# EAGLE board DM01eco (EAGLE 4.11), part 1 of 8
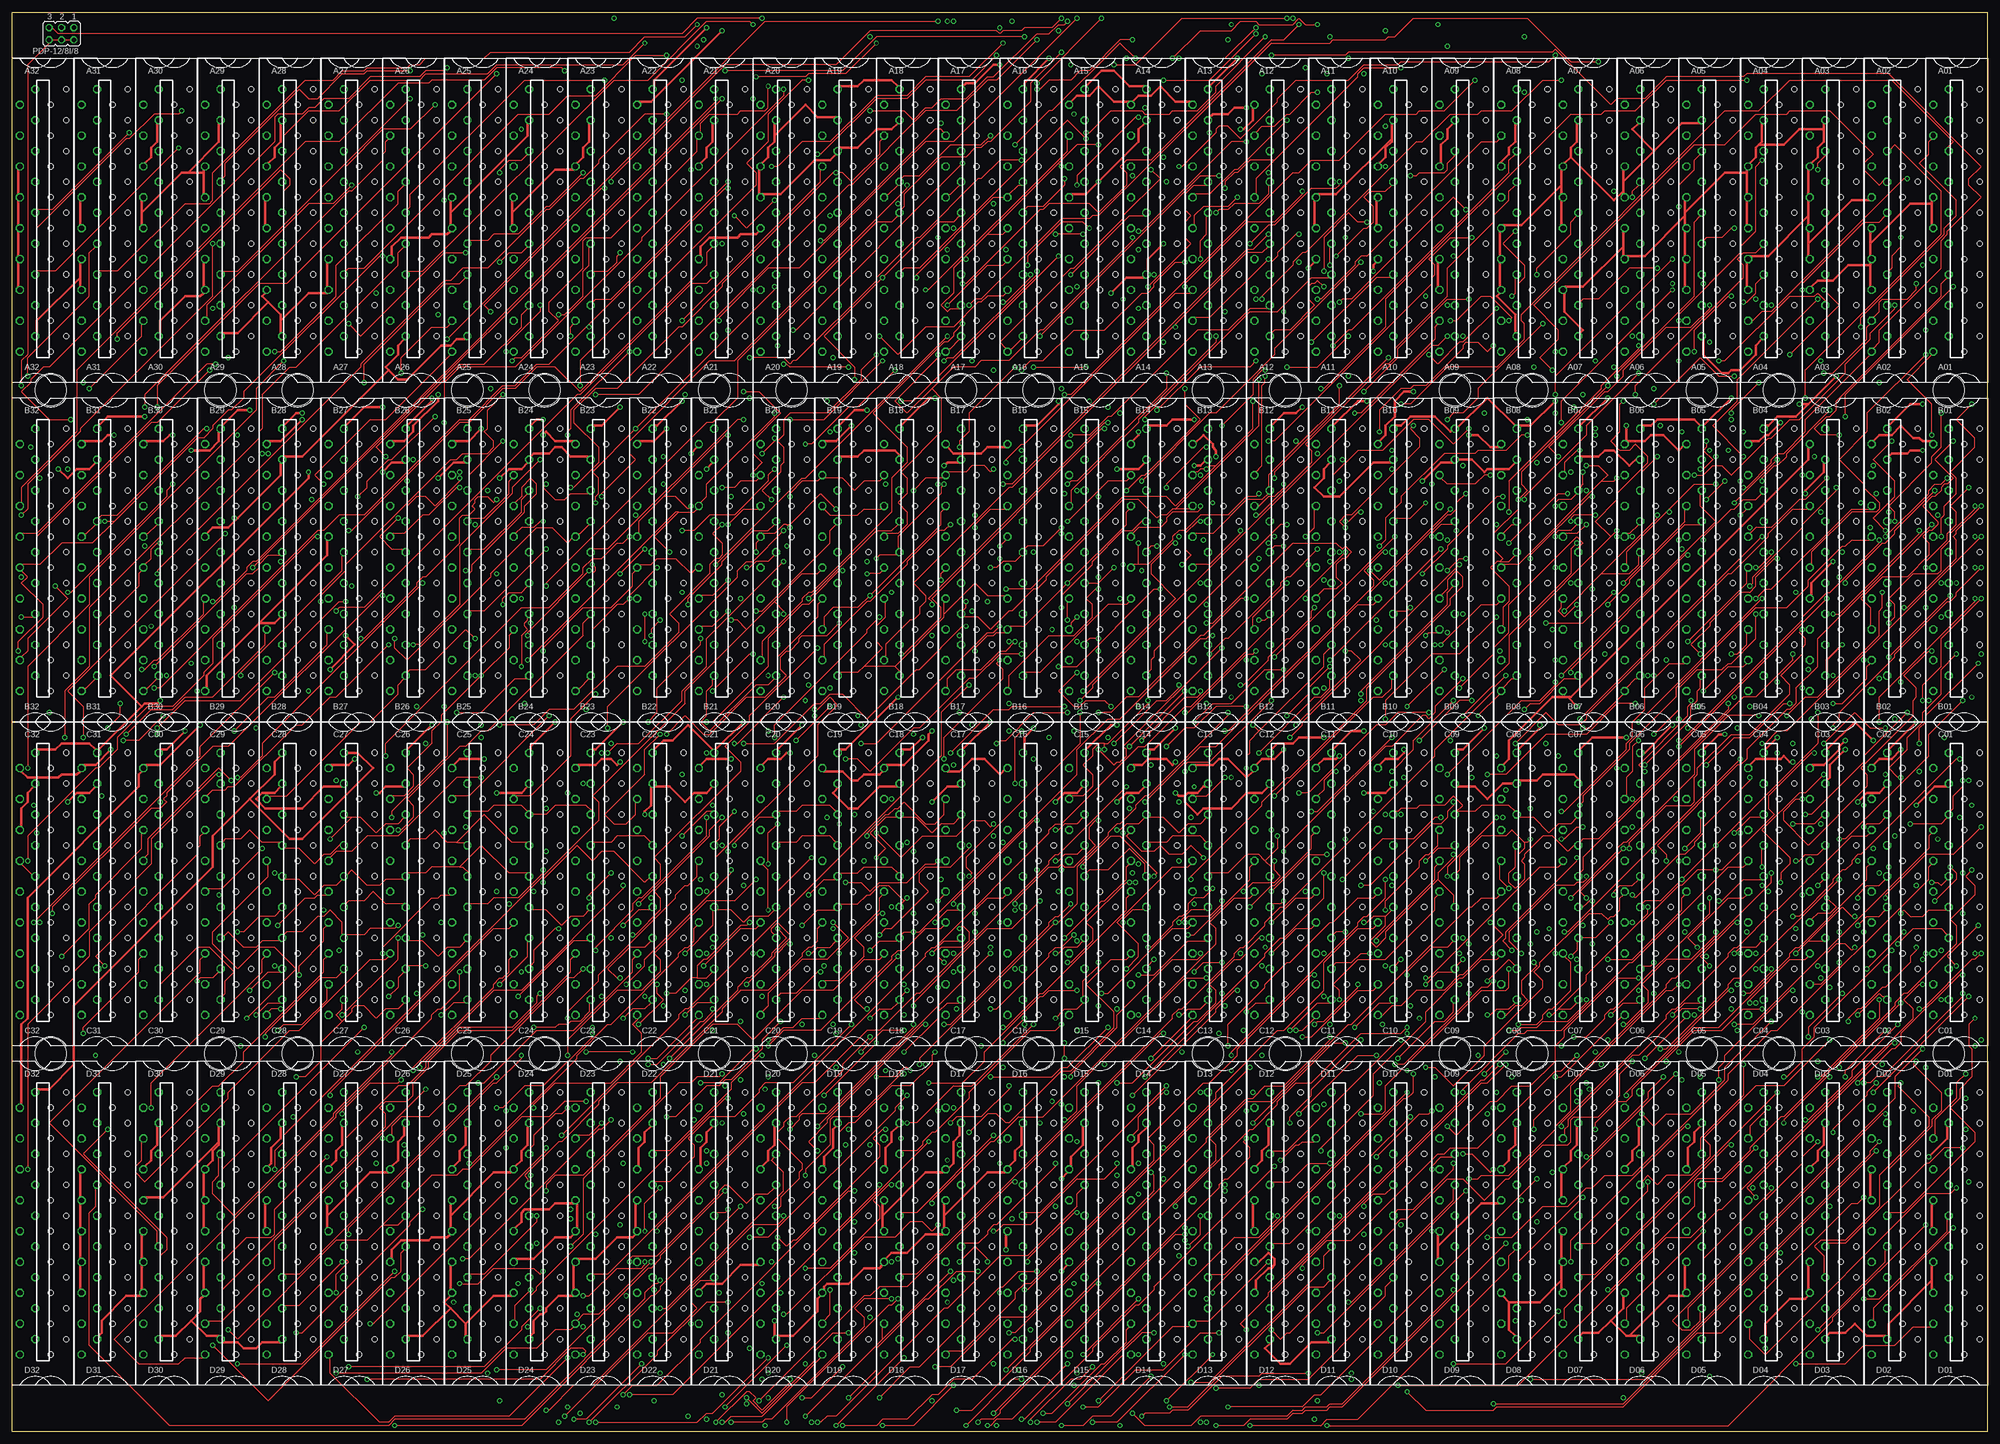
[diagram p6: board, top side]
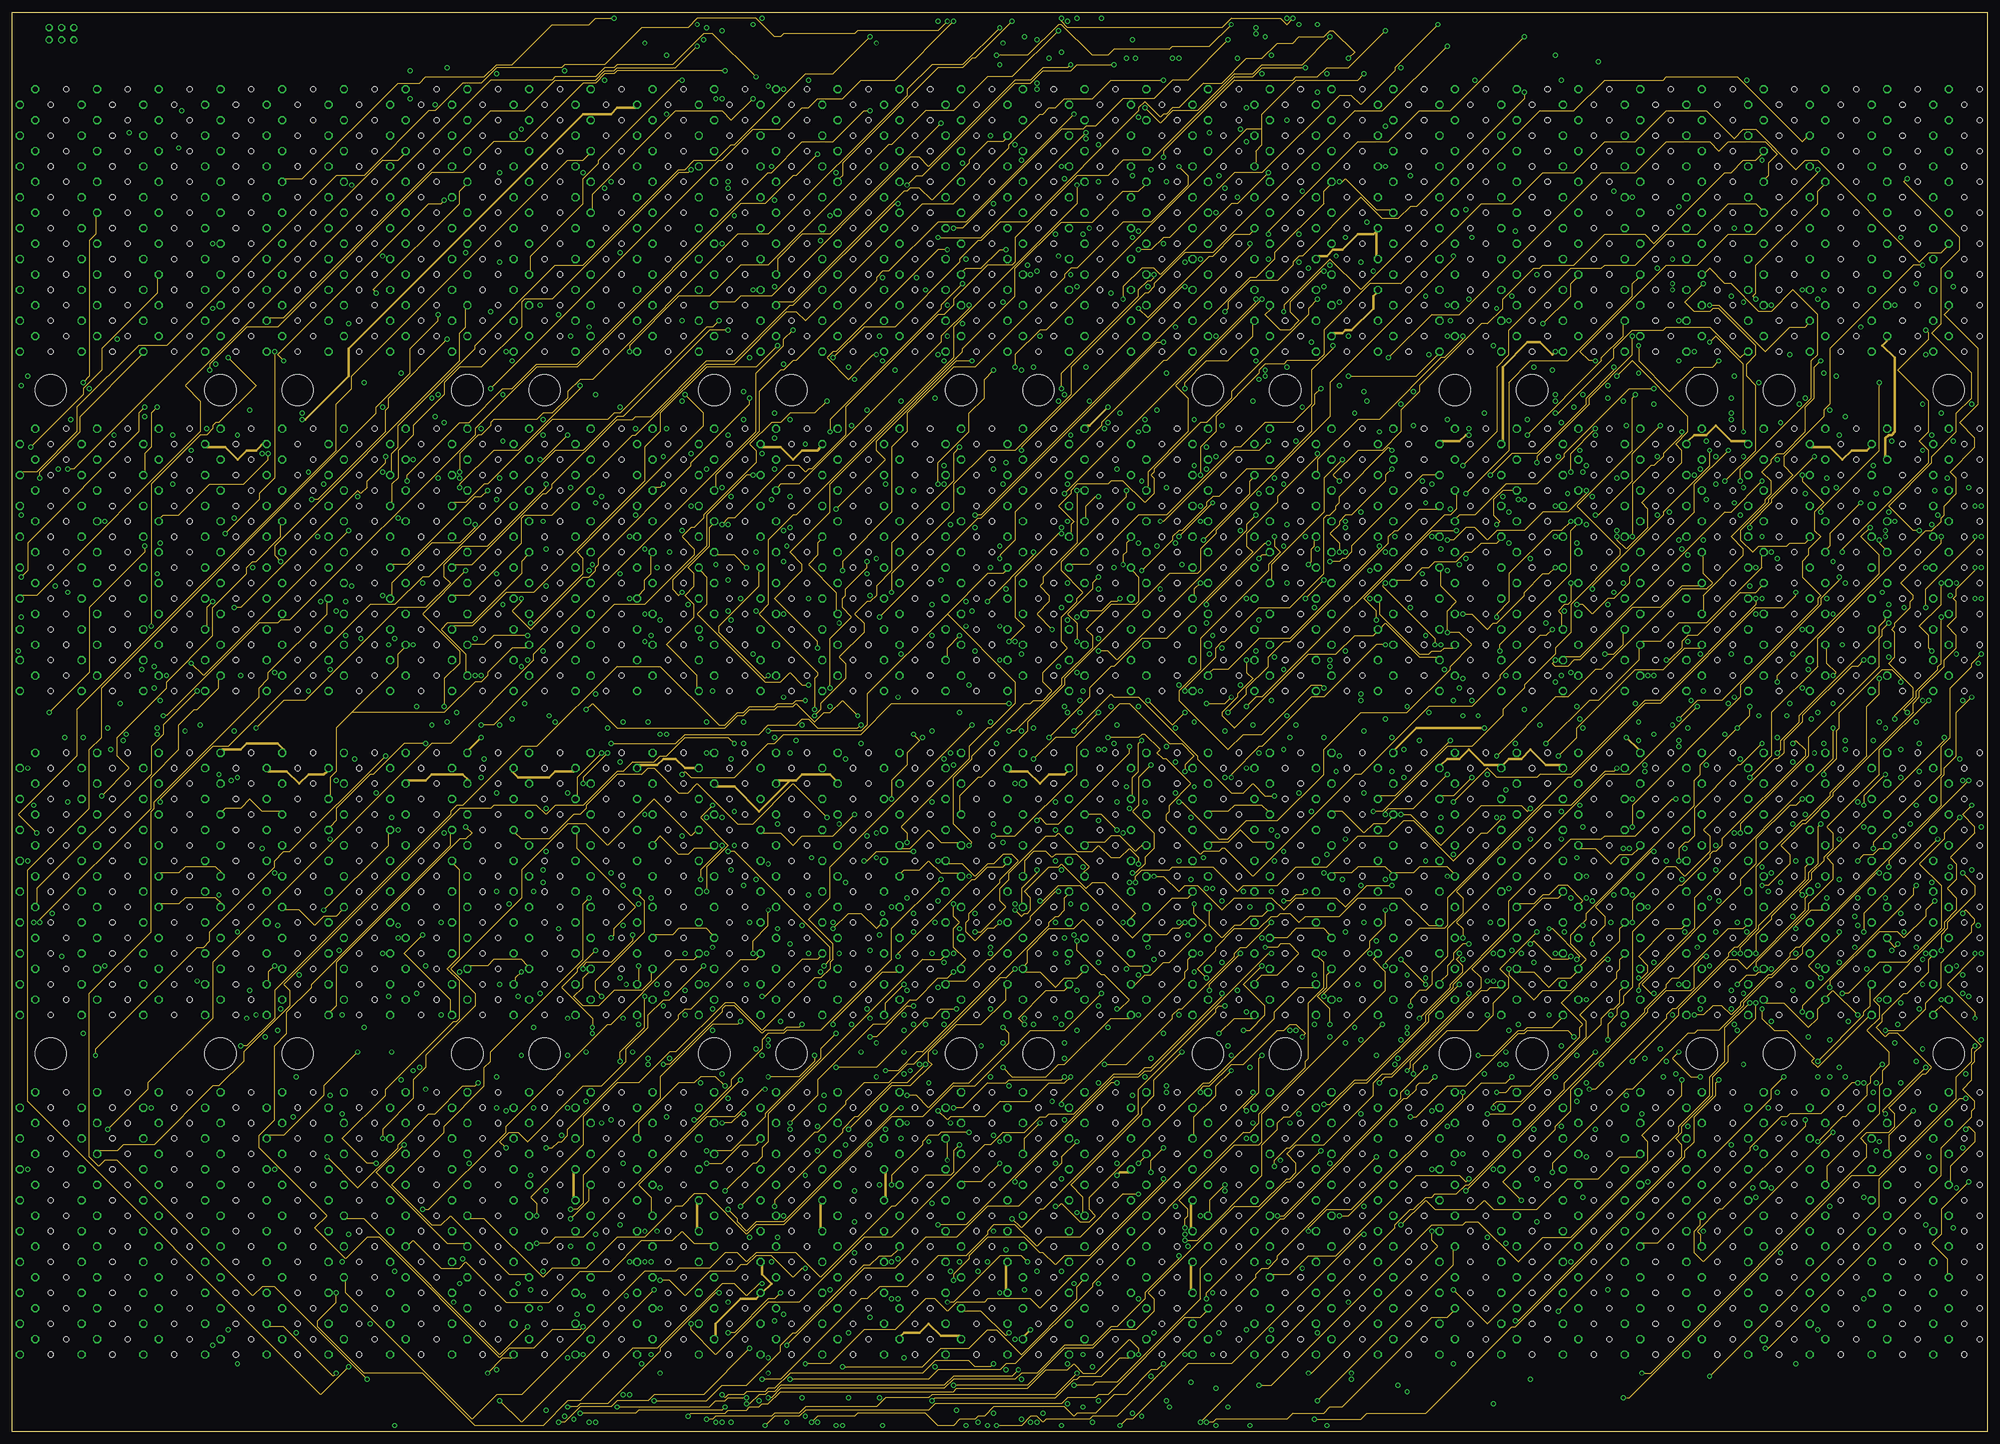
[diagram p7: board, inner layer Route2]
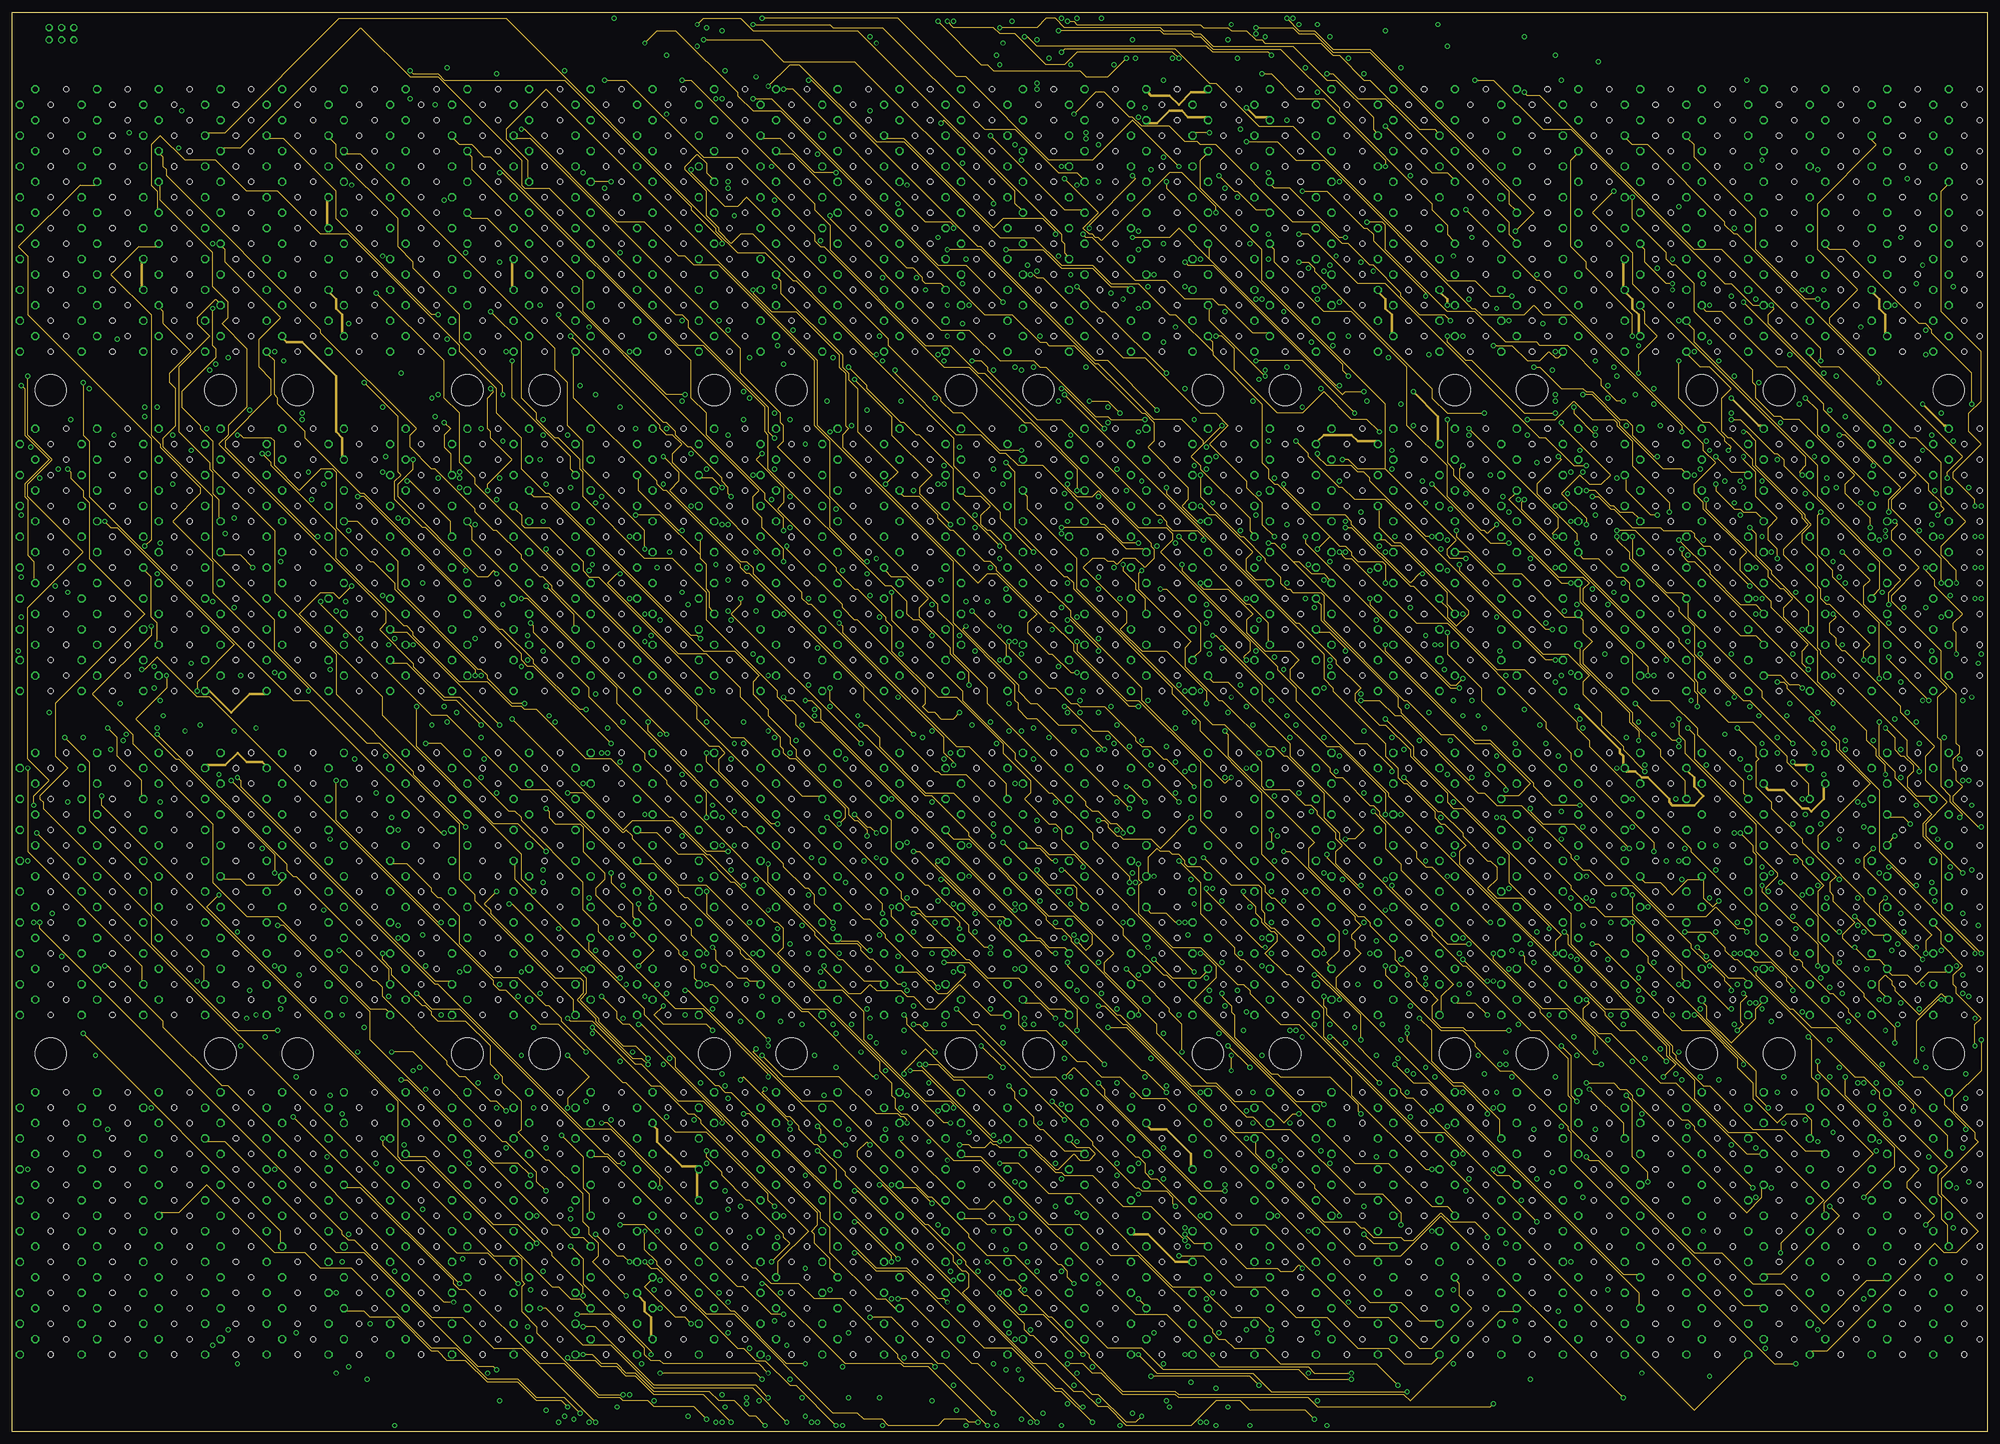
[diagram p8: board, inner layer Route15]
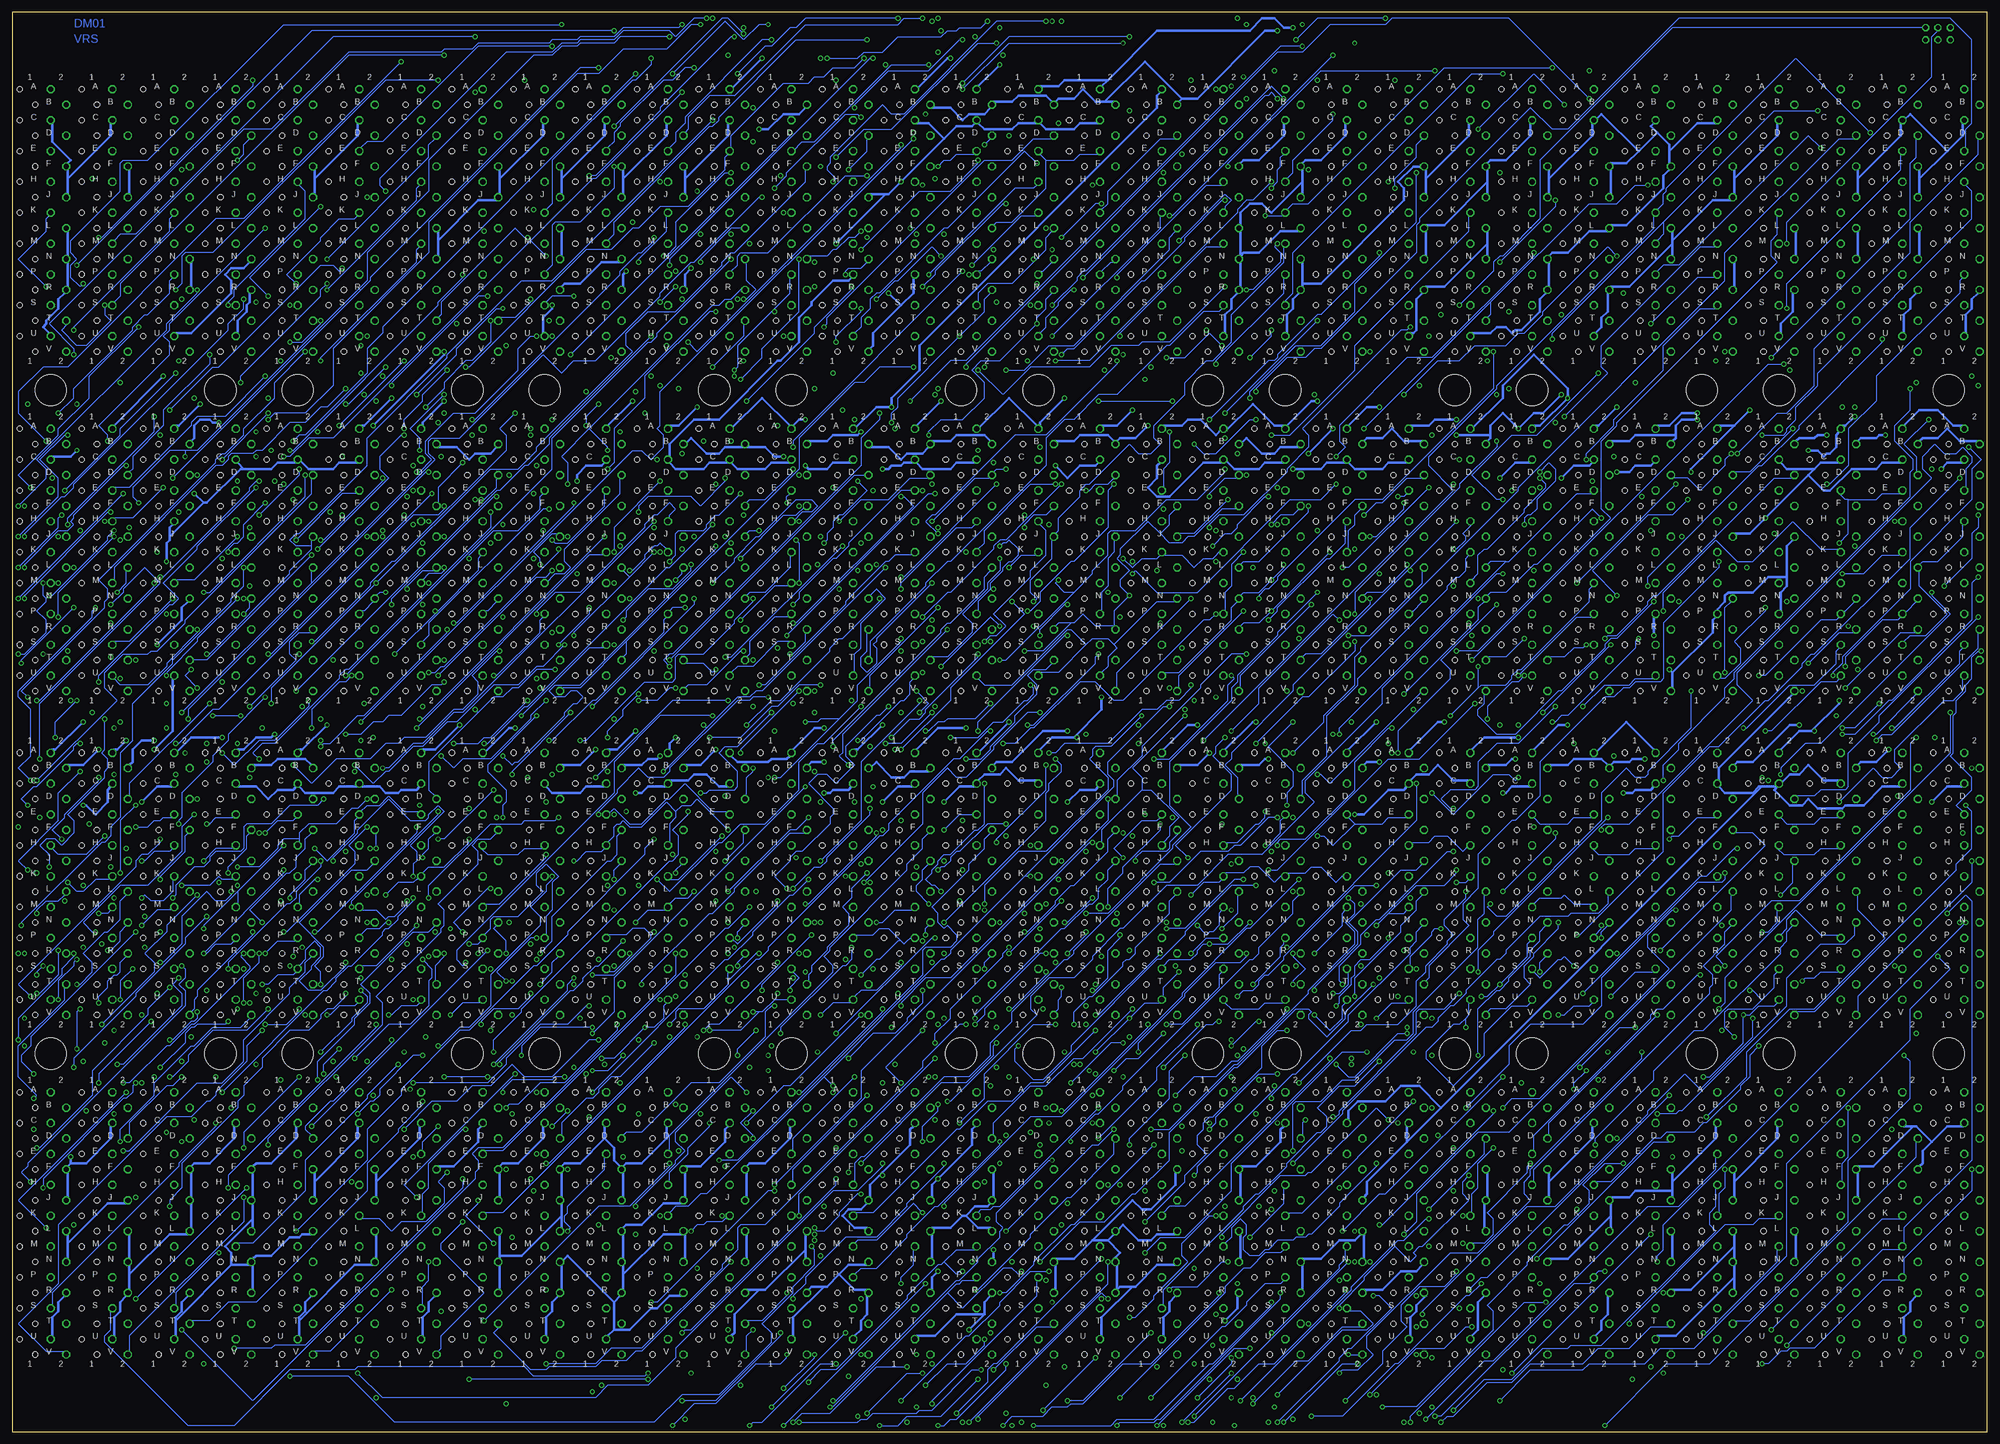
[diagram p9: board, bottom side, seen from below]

Size 406.4 x 292.1 mm. Coordinates in mm from the lower left corner, seen from the top.
Outline: 0,0 0,292.1 406.4,292.1 406.4,0 0,0
Copper layers (1*2*15*16): Top 0.035mm / dielectric 1.5mm / Route2 0.035mm / dielectric 0.15mm / Route15 0.035mm / dielectric 0.2mm / Bottom 0.035mm
Design rules "sierraproto": minimum track width 6mil, minimum drill 24mil, track to track 6mil, track to pad 6mil, pad to pad 10mil, via to via 6mil, smd to smd 6mil, copper to edge 25mil, drill to drill 10mil, minimum pad ring 10mil, minimum via ring 8mil, stop-mask expansion 0mil, vias tented up to drill 0mil, thermal gap 10mil
Net classes: 1 Supply: width 0.508 mm

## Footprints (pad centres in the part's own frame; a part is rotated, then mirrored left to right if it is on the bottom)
H807S = drill 1.092 octagon: A2 -1.587,28.575; B2 -4.763,25.4; C2 -1.587,22.225; D2 -4.763,19.05; E2 -1.587,15.875; F2 -4.763,12.7; H2 -1.587,9.525; J2 -4.763,6.35; K2 -1.587,3.175; L2 -4.763,0; M2 -1.587,-3.175; N2 -4.763,-6.35; P2 -1.587,-9.525; R2 -4.763,-12.7; S2 -1.587,-15.875; T2 -4.763,-19.05; U2 -1.587,-22.225; V2 -4.763,-25.4 | hole 1.092: 4.763,28.575; 1.587,25.4; 4.763,22.225; 1.587,19.05; 4.763,15.875; 1.587,12.7; 4.763,9.525; 1.587,6.35; 4.763,3.175; 1.587,0; 4.763,-3.175; 1.587,-6.35; 4.763,-9.525; 1.587,-12.7; 4.763,-15.875; 1.587,-19.05; 4.763,-22.225; 1.587,-25.4
JP3Q = drill 0.914 octagon: 1 -2.54,-1.27; 2 -2.54,1.27; 3 0,-1.27; 4 0,1.27; 5 2.54,-1.27; 6 2.54,1.27
CBLOCK = hole 6.452: 7.938,68.263; 42.862,68.263

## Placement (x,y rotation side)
A01  W021S  [H807S]  400.05,247.65 0 top
A02  W021S  [H807S]  387.35,247.65 0 top
A03  W021S  [H807S]  374.65,247.65 0 top
A04  W021S  [H807S]  361.95,247.65 0 top
A05  W021S  [H807S]  349.25,247.65 0 top
A06  W021S  [H807S]  336.55,247.65 0 top
A07  W021S  [H807S]  323.85,247.65 0 top
A08  W021S  [H807S]  311.15,247.65 0 top
A09  W021S  [H807S]  298.45,247.65 0 top
A10  W021S  [H807S]  285.75,247.65 0 top
A11  W021S  [H807S]  273.05,247.65 0 top
A12  S107S  [H807S]  260.35,247.65 0 top
A13  S107S  [H807S]  247.65,247.65 0 top
A14  W640S  [H807S]  234.95,247.65 0 top
A15  W640S  [H807S]  222.25,247.65 0 top
A16  S111S  [H807S]  209.55,247.65 0 top
A17  S111S  [H807S]  196.85,247.65 0 top
A18  S111S  [H807S]  184.15,247.65 0 top
A19  R202S  [H807S]  171.45,247.65 0 top
A20  W021S  [H807S]  158.75,247.65 0 top
A21  W021S  [H807S]  146.05,247.65 0 top
A22  EMPTYS  [H807S]  133.35,247.65 0 top
A23  W021S  [H807S]  120.65,247.65 0 top
A24  W021S  [H807S]  107.95,247.65 0 top
A25  W021S  [H807S]  95.25,247.65 0 top
A26  W021S  [H807S]  82.55,247.65 0 top
A27  W021S  [H807S]  69.85,247.65 0 top
A28  W021S  [H807S]  57.15,247.65 0 top
A29  W021S  [H807S]  44.45,247.65 0 top
A30  W021S  [H807S]  31.75,247.65 0 top
A31  W021S  [H807S]  19.05,247.65 0 top
A32  W021S  [H807S]  6.35,247.65 0 top
B01  EMPTYS  [H807S]  400.05,177.8 0 top
B02  R107S  [H807S]  387.35,177.8 0 top
B03  R603S  [H807S]  374.65,177.8 0 top
B04  S107S  [H807S]  361.95,177.8 0 top
B05  S107S  [H807S]  349.25,177.8 0 top
B06  S111S  [H807S]  336.55,177.8 0 top
B07  S107S  [H807S]  323.85,177.8 0 top
B08  S111S  [H807S]  311.15,177.8 0 top
B09  W005S  [H807S]  298.45,177.8 0 top
B10  S107S  [H807S]  285.75,177.8 0 top
B11  W005S  [H807S]  273.05,177.8 0 top
B12  S181S  [H807S]  260.35,177.8 0 top
B13  R107S  [H807S]  247.65,177.8 0 top
B14  S202S  [H807S]  234.95,177.8 0 top
B15  S107S  [H807S]  222.25,177.8 0 top
B16  S202S  [H807S]  209.55,177.8 0 top
B17  S202S  [H807S]  196.85,177.8 0 top
B18  S202S  [H807S]  184.15,177.8 0 top
B19  S202S  [H807S]  171.45,177.8 0 top
B20  S202S  [H807S]  158.75,177.8 0 top
B21  S202S  [H807S]  146.05,177.8 0 top
B22  R002S  [H807S]  133.35,177.8 0 top
B23  S111S  [H807S]  120.65,177.8 0 top
B24  W005S  [H807S]  107.95,177.8 0 top
B25  S107S  [H807S]  95.25,177.8 0 top
B26  S107S  [H807S]  82.55,177.8 0 top
B27  W640S  [H807S]  69.85,177.8 0 top
B28  W640S  [H807S]  57.15,177.8 0 top
B29  W640S  [H807S]  44.45,177.8 0 top
B30  S111S  [H807S]  31.75,177.8 0 top
B31  S111S  [H807S]  19.05,177.8 0 top
B32  S107S  [H807S]  6.35,177.8 0 top
C01  B141S  [H807S]  400.05,111.12 0 top
C02  B141S  [H807S]  387.35,111.12 0 top
C03  B141S  [H807S]  374.65,111.12 0 top
C04  B141S  [H807S]  361.95,111.12 0 top
C05  B141S  [H807S]  349.25,111.12 0 top
C06  B141S  [H807S]  336.55,111.12 0 top
C07  B141S  [H807S]  323.85,111.12 0 top
C08  B141S  [H807S]  311.15,111.12 0 top
C09  B141S  [H807S]  298.45,111.12 0 top
C10  B141S  [H807S]  285.75,111.12 0 top
C11  B141S  [H807S]  273.05,111.12 0 top
C12  B141S  [H807S]  260.35,111.12 0 top
C13  B141S  [H807S]  247.65,111.12 0 top
C14  B141S  [H807S]  234.95,111.12 0 top
C15  B141S  [H807S]  222.25,111.12 0 top
C16  B141S  [H807S]  209.55,111.12 0 top
C17  B141S  [H807S]  196.85,111.12 0 top
C18  B141S  [H807S]  184.15,111.12 0 top
C19  B141S  [H807S]  171.45,111.12 0 top
C20  B141S  [H807S]  158.75,111.12 0 top
C21  B141S  [H807S]  146.05,111.12 0 top
C22  B141S  [H807S]  133.35,111.12 0 top
C23  B141S  [H807S]  120.65,111.12 0 top
C24  B141S  [H807S]  107.95,111.12 0 top
C25  B141S  [H807S]  95.25,111.12 0 top
C26  B141S  [H807S]  82.55,111.12 0 top
C27  B141S  [H807S]  69.85,111.12 0 top
C28  B141S  [H807S]  57.15,111.12 0 top
C29  B141S  [H807S]  44.45,111.12 0 top
C30  B141S  [H807S]  31.75,111.12 0 top
C31  EMPTYS  [H807S]  19.05,111.12 0 top
C32  R302S  [H807S]  6.35,111.12 0 top
D01  W021S  [H807S]  400.05,41.27 0 top
D02  W021S  [H807S]  387.35,41.27 0 top
D03  W021S  [H807S]  374.65,41.27 0 top
D04  W021S  [H807S]  361.95,41.27 0 top
D05  W021S  [H807S]  349.25,41.27 0 top
D06  W021S  [H807S]  336.55,41.27 0 top
D07  W021S  [H807S]  323.85,41.27 0 top
D08  W021S  [H807S]  311.15,41.27 0 top
D09  W021S  [H807S]  298.45,41.27 0 top
D10  W021S  [H807S]  285.75,41.27 0 top
D11  W021S  [H807S]  273.05,41.27 0 top
D12  W021S  [H807S]  260.35,41.27 0 top
D13  W021S  [H807S]  247.65,41.27 0 top
D14  W021S  [H807S]  234.95,41.27 0 top
D15  W021S  [H807S]  222.25,41.27 0 top
D16  W021S  [H807S]  209.55,41.27 0 top
D17  W021S  [H807S]  196.85,41.27 0 top
D18  W021S  [H807S]  184.15,41.27 0 top
D19  W021S  [H807S]  171.45,41.27 0 top
D20  W021S  [H807S]  158.75,41.27 0 top
D21  W021S  [H807S]  146.05,41.27 0 top
D22  W021S  [H807S]  133.35,41.27 0 top
D23  W021S  [H807S]  120.65,41.27 0 top
D24  W021S  [H807S]  107.95,41.27 0 top
D25  W021S  [H807S]  95.25,41.27 0 top
D26  W021S  [H807S]  82.55,41.27 0 top
D27  W021S  [H807S]  69.85,41.27 0 top
D28  W021S  [H807S]  57.15,41.27 0 top
D29  W021S  [H807S]  44.45,41.27 0 top
D30  W021S  [H807S]  31.75,41.27 0 top
D31  W021S  [H807S]  19.05,41.27 0 top
D32  EMPTYS  [H807S]  6.35,41.27 0 top
PDP-12/8I/8  [JP3Q]  10.16,287.65 180 top
U$1  [CBLOCK]  0,9.53 0 top
U$2  [CBLOCK]  50.8,9.53 0 top
U$3  [CBLOCK]  101.6,9.53 0 top
U$4  [CBLOCK]  152.4,9.53 0 top
U$5  [CBLOCK]  203.2,9.53 0 top
U$6  [CBLOCK]  254,9.53 0 top
U$7  [CBLOCK]  304.8,9.53 0 top
U$8  [CBLOCK]  355.6,9.53 0 top
U$9  [CBLOCK]  0,146.05 0 top
U$10  [CBLOCK]  50.8,146.05 0 top
U$11  [CBLOCK]  101.6,146.05 0 top
U$12  [CBLOCK]  152.4,146.05 0 top
U$13  [CBLOCK]  203.2,146.05 0 top
U$14  [CBLOCK]  254,146.05 0 top
U$15  [CBLOCK]  304.8,146.05 0 top
U$16  [CBLOCK]  355.6,146.05 0 top

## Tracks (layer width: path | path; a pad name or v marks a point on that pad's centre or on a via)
1-CA_INH  (via drill 0.61)
  Top 0.152: v153.03,278.76 163.19,278.76 163.83,279.4 171.45,279.4 v177.8,285.75 | v210.82,276.22 211.46,276.22 213.36,278.13 217.81,278.13 219.71,280.03 221.62,280.03 227.97,286.38 v230.5,286.38
  Route2 0.152: v153.03,278.76 144.15,287.65 142.24,287.65 135.89,281.3 124.46,281.3 123.83,280.67 121.92,280.67 120.02,278.76 111.76,278.76 111.12,278.13 98.42,278.13 35.56,215.27 38.73,212.09 38.73,205.74 5.08,172.09 1.91,172.09 B32.N2
  Bottom 0.152: v177.8,285.75 201.29,285.75 v210.82,276.22 | v230.5,286.38 245.11,286.38 260.99,270.51 260.99,269.88 262.25,268.6 262.89,268.6 282.57,248.92 282.57,246.38 283.85,245.11 A10.M2
1-CA_INH0  (via drill 0.61)
  Top 0.152: v207.65,10.79 205.74,10.79 v196.22,1.27 | v147.32,26.67 142.88,26.67 132.72,16.51 132.72,15.88 v118.75,1.91 | v19.05,95.89 17.14,97.79 38.1,118.75 38.1,120.02 38.73,120.65 38.73,122.56 39.37,123.19 C29.F2
  Route2 0.152: v278.13,40.64 277.5,40.64 250.82,13.97 241.94,13.97 230.5,2.54 229.24,2.54 v227.97,1.27
  Route15 0.152: v278.13,40.64 280.04,38.73 283.85,38.73 D10.M2 | v90.81,26.67 88.9,26.67 44.45,71.12 43.18,71.12 31.11,83.19 31.11,84.46 19.68,95.89 v19.05,95.89
  Bottom 0.152: v227.97,1.27 224.16,1.27 222.25,3.18 215.26,3.18 v207.65,10.79 | v196.22,1.27 180.34,1.27 179.07,2.54 171.45,2.54 160.02,13.97 159.38,13.97 147.32,26.04 v147.32,26.67 | v118.75,1.91 118.75,3.18 95.25,26.67 v90.81,26.67
1-CA_INH1  (via drill 0.61)
  Top 0.152: v117.47,27.94 118.75,27.94 124.46,33.66 129.54,33.66 130.18,34.29 v130.18,34.92 | v169.54,1.27 v183.51,15.24 | v194.31,4.45 197.49,4.45 209.55,16.51 209.55,17.14 222.88,30.48 v223.52,30.48
  Route15 0.152: v42.55,110.49 40.01,107.95 111.12,36.83 111.12,36.2 117.47,29.84 v117.47,27.94 | v130.18,34.92 131.44,33.66 132.72,33.66 149.22,17.14 150.5,17.14 153.03,14.61 154.94,14.61 160.02,9.53 161.29,9.53 v169.54,1.27
  Bottom 0.152: v42.55,110.49 40.01,113.03 40.01,116.84 C29.J2 | v183.51,15.24 v194.31,4.45 | v223.52,30.48 223.52,31.75 220.98,34.29 220.98,37.47 D15.M2
1-CA_INH2  (via drill 0.61)
  Top 0.152: v51.44,120.02 43.18,111.76 40.01,111.76 C29.L2
  Route15 0.152: v83.19,90.17 86.36,87 92.08,87 121.92,57.15 122.56,57.15 124.46,55.24 v125.73,55.24
  Bottom 0.152: v51.44,120.02 52.07,120.02 57.78,114.3 59.05,114.3 v83.19,90.17 | v125.73,55.24 125.73,54.61 133.35,46.99 133.35,46.35 139.06,40.64 139.7,40.64 140.34,40.01 142.24,40.01 142.88,39.37 146.05,39.37 147.96,37.47 148.59,37.47 149.86,36.2 151.76,36.2 153.03,37.47 153.03,40.01 152.4,40.64 152.4,42.55 153.67,43.81 155.57,41.91 155.57,40.01 156.84,38.73 D20.M2
1-CA_INH3  (via drill 0.61)
  Route2 0.152: v80.64,59.05 74.93,53.34 89.53,38.73 93.34,38.73 D25.M2
  Bottom 0.152: v80.64,59.05 80.64,60.32 68.58,72.39 68.58,74.3 60.33,82.55 58.42,82.55 42.55,98.43 42.55,99.7 41.27,100.97 41.27,102.87 40.01,104.14 C29.N2
1-CA_INH4
  Top 0.152: D30.M2 29.84,38.73 29.84,41.27 7.62,63.5 38.73,94.62 38.73,97.16 39.37,97.79 C29.R2
1-CA_INH5  (via drill 0.61)
  Top 0.152: v10.79,142.88 10.79,152.4 15.88,157.48 15.88,169.55 50.8,204.47 50.8,205.74 51.44,206.38 51.44,213.36 57.15,219.08 58.42,219.08 79.38,240.03 79.38,242.57 80.64,243.84 A26.M2
  Route15 0.152: v10.79,142.88 15.88,137.8 15.88,125.73 28.57,113.03 28.57,106.68 39.37,95.89 39.37,92.71 C29.T2
1-CA_INH6  (via drill 0.61)
  Top 0.152: v3.17,217.17 3.17,220.98 15.88,233.68 15.88,242.57 17.14,243.84 A31.M2
  Route15 0.152: v4.45,128.91 4.45,130.81 7.62,133.98 3.17,138.43 3.17,169.55 14.61,180.97 3.17,192.41 3.17,194.94 8.26,200.03 3.17,205.11 v3.17,217.17
  Bottom 0.152: v4.45,128.91 3.17,127.64 3.17,120.02 6.35,116.84 6.35,115.57 35.56,86.36 39.37,86.36 C29.V2
-15V  (via drill 0.61)
  Top 0.508: v146.05,288.29 131.44,273.69 128.91,273.69 A22.B2 | A15.B2 217.81,273.69 219.07,274.95 221.62,274.95 223.52,276.86 226.69,273.69 229.87,273.69 A14.B2 230.5,273.69 231.78,274.95 234.31,274.95 236.22,276.86 239.4,273.69 242.57,273.69 A13.B2 | v252.73,267.97 253.37,267.97 255.27,269.88 255.27,272.41 A12.B2 | v33.02,205.11 32.38,205.11 31.11,203.84 27.3,203.84 B30.B2 | v59.69,208.28 55.24,203.84 52.7,203.84 B28.B2 | v20.95,205.11 19.68,205.11 18.41,203.84 14.61,203.84 B31.B2 | v96.52,206.38 93.98,203.84 90.81,203.84 B25.B2 | v109.22,205.11 109.86,205.74 111.76,203.84 115.57,203.84 B23.B2 | v299.72,205.11 301.62,205.11 304.17,202.56 306.07,202.56 B08.B2 | v172.72,207.01 169.54,203.84 167,203.84 B19.B2 | B16.B2 204.47,202.56 200.66,202.56 199.39,201.3 193.68,201.3 192.41,202.56 B17.B2 | v231.78,205.74 231.78,205.11 230.5,203.84 B14.B2 | v247.65,200.66 247.65,201.93 247.01,202.56 247.01,203.2 245.11,205.11 243.21,203.2 B13.B2 | v288.29,214 286.38,214 284.48,212.09 284.48,208.91 282.57,207.01 282.57,205.11 281.31,203.84 B10.B2 | v134.62,206.38 132.08,203.84 128.91,203.84 B22.B2 | v139.7,201.3 140.97,202.56 B21.B2 | v87.63,213.36 87.63,212.09 82.55,207.01 82.55,205.74 80.64,203.84 78.11,203.84 B26.B2 | C32.B2 1.91,135.89 3.17,134.62 9.53,134.62 10.16,135.25 13.34,135.25 13.97,135.89 C31.B2 14.61,137.16 17.14,137.16 v20.32,140.34 | D32.B2 1.91,67.31 1.91,83.82 3.17,85.09 3.17,109.86 26.04,132.72 26.04,135.25 26.67,135.89 C30.B2 27.3,137.16 30.48,137.16 v38.73,145.41 | v70.48,138.43 69.22,137.16 65.41,137.16 C27.B2 | v97.16,138.43 92.08,138.43 90.81,137.16 C25.B2
  Top 0.508: v377.19,142.24 375.92,140.97 375.92,140.34 372.75,137.16 370.2,137.16 C03.B2 | v388.62,140.34 386.71,138.43 384.18,138.43 382.9,137.16 C02.B2 | v366.39,137.8 365.76,137.8 364.49,139.06 363.86,138.43 358.77,138.43 357.5,137.16 C04.B2 | 332.11,203.84 335.92,203.84 337.19,205.11 339.73,205.11 342.9,201.93 344.17,203.2 B05.B2 | 332.11,203.84 B06.B2 332.11,203.84 | B01.B2 394.97,203.84 393.06,203.84 392.43,204.47 391.16,204.47 388.62,207.01 386.71,205.11 384.18,205.11 382.9,203.84 B02.B2 | v363.86,207.65 361.31,205.11 360.68,205.11 359.41,203.84 357.5,203.84 B04.B2 | C19.B2 167,135.89 170.81,135.89 172.72,133.98 173.99,133.98 175.26,135.25 178.44,135.25 179.07,135.89 C18.B2 179.71,137.16 183.51,137.16 188.59,142.24 188.59,143.51 v189.23,144.15 | v147.96,138.43 142.88,138.43 141.6,137.16 C21.B2 | v160.02,139.7 159.38,139.7 158.12,138.43 155.57,138.43 154.31,137.16 C20.B2 | C17.B2 192.41,135.89 194.94,135.89 197.49,138.43 200.03,138.43 203.2,135.25 204.47,136.53 C16.B2 | C13.B2 243.21,137.16 247.01,137.16 248.28,138.43 250.19,138.43 254,134.62 255.27,135.89 C12.B2 255.91,137.16 257.18,138.43 259.71,138.43 v261.62,140.34 | v273.05,139.06 272.42,138.43 269.88,138.43 268.61,137.16 C11.B2 | v286.38,140.34 286.38,139.7 285.12,138.43 282.57,138.43 281.31,137.16 C10.B2 | v239.4,137.8 238.76,137.16 237.49,138.43 233.68,138.43 232.41,137.16 230.5,137.16 C14.B2 | 320.04,151.13 316.87,151.13 307.98,142.24 307.98,138.43 306.7,137.16 C08.B2 | 320.04,151.13 320.68,151.13 369.57,200.03 369.57,202.56 B03.B2 | 320.04,151.13 v321.94,149.22 | v125.09,137.8 124.46,137.16 123.19,138.43 121.28,138.43 120.02,137.16 116.2,137.16 C23.B2
  Top 0.508: 332.11,203.84 v332.11,207.01
  Route2 0.508: B29.B2 40.01,202.56 43.81,202.56 46.35,200.03 48.26,201.93 50.16,201.93 52.07,203.84 B28.B2 | v299.72,205.11 299.08,205.11 297.81,203.84 294,203.84 B09.B2 | B20.B2 154.31,202.56 158.12,202.56 160.66,200.03 162.56,201.93 165.74,201.93 166.37,202.56 B19.B2 | v59.69,208.28 60.33,208.28 69.22,217.17 69.22,222.89 117.47,271.14 123.19,271.14 124.46,272.41 128.27,272.41 A22.B2 | C23.B2 115.57,135.89 111.76,135.89 110.49,134.62 104.14,134.62 102.87,135.89 C24.B2 | C28.B2 52.7,135.89 56.52,135.89 59.05,133.35 60.96,135.25 64.14,135.25 64.77,135.89 C27.B2 | B04.B2 356.87,203.84 353.69,203.84 350.52,207.01 348.62,205.11 346.07,205.11 344.81,203.84 B05.B2 | B03.B2 370.2,202.56 374.01,202.56 376.56,200.03 378.46,201.93 381.63,201.93 382.27,202.56 B02.B2 | C22.B2 128.91,137.16 132.72,137.16 133.99,138.43 136.53,138.43 138.43,136.53 140.97,136.53 C21.B2 | C16.B2 205.1,135.89 208.91,135.89 211.46,133.35 213.36,135.25 216.53,135.25 217.17,135.89 C15.B2 | C09.B2 294,137.16 295.27,138.43 297.81,138.43 299.72,140.34 302.89,137.16 306.07,137.16 C08.B2 306.7,137.16 307.98,138.43 310.51,138.43 312.42,140.34 315.6,137.16 318.77,137.16 C07.B2 | v317.5,222.25 316.87,221.62 314.32,224.16 311.79,224.16 306.7,219.08 306.7,203.84 B08.B2
  Route15 0.508: B10.B2 280.67,203.84 276.86,203.84 275.59,205.11 269.88,205.11 268.61,203.84 B11.B2 | v288.29,214 293.37,208.91 293.37,203.84 B09.B2 | C29.B2 40.01,137.16 43.81,137.16 46.35,139.7 48.26,137.8 51.44,137.8 52.07,137.16 C28.B2 | C05.B2 344.81,135.89 346.07,134.62 346.07,132.72 347.98,130.81 346.07,128.91 341.63,128.91 341,129.54 341,130.18 336.55,134.62 335.28,134.62 334.01,135.89 332.11,135.89 C06.B2 331.47,137.16 331.47,139.06 330.83,139.7 330.83,140.34 v321.94,149.22 | v366.39,137.8 367.03,137.16 369.57,137.16 C03.B2
  Bottom 0.508: v146.05,288.29 148.59,288.29 162.56,274.32 165.74,274.32 | 165.74,274.32 166.37,273.69 A19.B2 | 181.61,273.69 183.51,273.69 186.06,276.22 187.96,274.32 191.13,274.32 191.77,273.69 A17.B2 192.41,273.69 193.68,274.95 199.39,274.95 200.66,273.69 204.47,273.69 A16.B2 205.1,272.41 206.38,271.14 209.55,271.14 210.82,269.88 213.36,272.41 217.17,272.41 A15.B2 | 181.61,273.69 179.71,273.69 A18.B2 | v252.73,267.97 250.82,267.97 247.65,271.14 244.47,271.14 243.21,272.41 A13.B2 | 165.74,274.32 173.35,281.94 181.61,273.69 | B32.B2 1.91,203.84 5.71,203.84 8.26,206.38 10.16,204.47 13.34,204.47 13.97,203.84 B31.B2 | v33.02,205.11 34.92,205.11 35.56,204.47 38.73,204.47 39.37,203.84 B29.B2 | v59.69,208.28 62.87,208.28 64.14,207.01 64.14,205.11 | 64.14,205.11 64.14,204.47 64.77,203.84 B27.B2 | 64.14,205.11 72.39,205.11 73.66,203.84 77.47,203.84 B26.B2 | v20.95,205.11 22.23,205.11 22.86,204.47 26.04,204.47 26.67,203.84 B30.B2 | B23.B2 116.2,203.84 120.02,203.84 122.56,206.38 124.46,204.47 127.64,204.47 128.27,203.84 B22.B2 | 102.23,205.11 102.23,204.47 102.87,203.84 B24.B2 | 102.23,205.11 102.23,207.01 99.69,209.55 v96.52,206.38 93.34,209.55 91.44,209.55 v87.63,213.36 | v109.22,205.11 102.23,205.11 | B07.B2 318.77,202.56 314.96,202.56 312.42,200.03 311.15,201.3 307.98,201.3 306.7,202.56 B08.B2 | B11.B2 267.97,203.2 266.7,204.47 263.52,201.3 260.99,201.3 259.71,202.56 255.91,202.56 B12.B2 255.27,202.56 251.46,202.56 249.56,200.66 v247.65,200.66 | B21.B2 141.6,202.56 145.41,202.56 146.69,201.3 149.22,201.3 152.4,204.47 153.67,203.2 B20.B2 | v172.72,207.01 175.26,204.47 178.44,204.47 179.07,203.84 B18.B2 179.71,203.84 180.97,205.11 186.69,205.11 187.96,203.84 191.77,203.84 B17.B2
  Bottom 0.508: B16.B2 205.1,203.84 206.38,205.11 212.09,205.11 213.36,203.84 217.17,203.84 B15.B2 217.81,202.56 219.07,201.3 222.25,201.3 223.52,200.03 226.06,202.56 229.87,202.56 B14.B2 | v231.78,205.74 232.41,205.11 237.49,205.11 238.76,203.84 242.57,203.84 B13.B2 | v139.7,201.3 v134.62,206.38 | v20.32,140.34 22.86,137.8 26.04,137.8 26.67,137.16 C30.B2 | v70.48,138.43 73.03,138.43 73.66,137.8 76.83,137.8 77.47,137.16 C26.B2 78.11,137.16 79.38,138.43 85.09,138.43 86.36,137.16 90.17,137.16 C25.B2 | v97.16,138.43 97.79,138.43 99.06,137.16 102.87,137.16 C24.B2 | v377.19,142.24 379.73,142.24 381.63,140.34 381.63,137.8 382.27,137.16 C02.B2 | v388.62,140.34 391.8,137.16 394.97,137.16 C01.B2 | C04.B2 356.87,137.16 353.06,137.16 351.79,138.43 346.07,138.43 344.81,137.16 C05.B2 | v363.86,207.65 365.12,207.65 365.76,208.28 367.67,208.28 368.94,207.01 368.94,204.47 369.57,203.84 B03.B2 | v147.96,138.43 148.59,138.43 149.86,137.16 153.67,137.16 C20.B2 | v160.02,139.7 162.56,137.16 166.37,137.16 C19.B2 | C15.B2 217.81,135.89 221.62,135.89 222.88,134.62 225.43,134.62 228.6,137.8 229.87,136.53 C14.B2 | v261.62,140.34 264.8,137.16 267.97,137.16 C11.B2 | v273.05,139.06 273.69,138.43 275.59,138.43 276.86,137.16 280.67,137.16 C10.B2 | v286.38,140.34 289.56,137.16 293.37,137.16 C09.B2 | v239.4,137.8 241.94,137.8 242.57,137.16 C13.B2 | v189.23,144.15 194.31,144.15 200.66,137.8 203.84,137.8 204.47,137.16 C16.B2 | v125.09,137.8 127.64,137.8 128.27,137.16 C22.B2 | v38.73,145.41 40.64,145.41 48.26,137.8 51.44,137.8 52.07,137.16 C28.B2 | v317.5,222.25 317.5,221.62 v332.11,207.01
-AC_CLEAR  (via drill 0.61)
  Top 0.152: v261.62,119.38 261.62,120.02 282.57,140.97 283.85,140.97 290.19,147.32 290.83,147.32 291.46,146.69 292.74,147.96 292.74,149.22 v298.45,154.94 | v279.4,171.45 279.4,172.72 295.27,188.59 295.91,188.59 297.18,189.87 297.18,191.14 v299.08,193.04
  Route2 0.152: v299.08,193.04 307.98,201.93 307.98,215.9 312.42,220.34 320.04,220.34 333.38,233.68 333.38,236.22 334.64,237.49 A06.P2
  Route15 0.152: v261.62,119.38 262.89,119.38 276.23,106.05 276.23,105.41 277.5,104.14 275.59,102.23 275.59,101.6 276.23,100.97 276.23,99.7 277.5,98.43 272.42,93.34 272.42,91.44 331.47,32.38 334.64,32.38 D06.P2 | v298.45,154.94 297.18,153.67 295.91,153.67 279.4,170.18 v279.4,171.45
-BAC0  (via drill 0.61)
  Top 0.152: v401.95,73.66 400.05,71.75 400.05,68.58 395.61,64.14 395.61,60.96 D01.D2 | v388.62,134.62 387.99,134.62 386.08,136.53 389.89,140.34 389.89,142.88 393.06,146.05 393.06,147.96 396.88,151.77 396.88,156.84 v400.05,160.02 | v393.7,177.8 393.7,179.07 398.14,183.52 398.14,184.78 400.05,186.69 400.05,189.23 398.78,190.5 v402.59,194.31 | v380.37,227.33 380.37,229.24 397.51,246.38 397.51,247.65 400.05,250.19 400.05,253.37 392.43,260.99 394.33,262.89 394.33,265.43 394.97,266.06 A01.D2
  Route2 0.152: v381,102.87 381,106.68 v396.24,121.92
  Route15 0.152: v400.05,160.02 400.05,164.47 399.42,165.1 399.42,166.37 401.32,168.28 395.61,173.99 395.61,175.26 393.7,177.16 v393.7,177.8
  Bottom 0.152: v401.95,73.66 404.5,76.2 404.5,77.47 402.59,79.38 402.59,81.28 v381,102.87 | v396.24,121.92 398.14,123.83 395.61,126.37 395.61,127 388.62,133.98 v388.62,134.62 | v402.59,194.31 405.13,196.85 396.88,205.11 396.88,206.38 390.52,212.72 390.52,217.17 v380.37,227.33
-BAC1  (via drill 0.61)
  Top 0.152: v274.32,186.06 273.05,187.33 274.32,188.59 275.59,188.59 289.56,202.56 289.56,204.47 287.65,206.38 v288.29,207.01 | v285.75,211.46 287.65,211.46 295.27,219.08 305.44,219.08 311.15,224.79 311.15,227.97 310.51,228.6 310.51,229.87 352.43,271.78 359.41,271.78 365.76,278.13 386.71,278.13 399.42,265.43 398.14,264.16 A01.E2
  Route15 0.152: v274.32,186.06 275.59,186.06 287.65,173.99 288.29,173.99 305.44,156.84 311.15,156.84 321.94,146.05 321.94,144.78 324.49,142.24 324.49,140.97 345.44,120.02 345.44,119.38 358.77,106.05 358.77,100.33 398.14,60.96 398.14,57.78 D01.E2
  Bottom 0.152: v288.29,207.01 288.29,208.91 v285.75,211.46
-BAC2  (via drill 0.61)
  Top 0.152: v386.08,166.37 387.35,167.64 387.35,170.18 386.08,171.45 391.16,176.53 396.24,176.53 396.88,177.16 396.88,181.61 398.78,183.52 398.78,184.78 403.86,189.87 v403.86,190.5
  Route2 0.152: v401.95,62.23 402.59,62.87 403.86,61.59 403.86,59.69 398.78,54.61 398.78,51.43 D01.H2 | v355.6,123.19 355.6,125.09 369.57,139.06 369.57,142.88 384.18,157.48 384.18,163.19 384.81,163.83 384.81,165.1 v386.08,166.37
  Route15 0.152: v401.95,62.23 401.95,62.87 397.51,67.31 397.51,68.58 393.06,73.03 391.16,73.03 377.82,86.36 377.82,87 374.65,90.17 374.01,90.17 368.3,95.89 368.3,96.52 367.67,97.16 367.03,97.16 365.76,98.43 365.76,99.7 358.77,106.68 358.77,118.75 358.14,119.38 358.14,120.65 v355.6,123.19 | v403.86,190.5 403.86,191.77 399.42,196.22 399.42,197.49 405.13,203.2 402.59,205.74 402.59,209.55 405.13,212.09 405.13,222.25 396.88,230.5 396.88,255.27 398.14,256.54 A01.H2
-BAC3  (via drill 0.61)
  Top 0.152: v381,27.3 384.18,27.3 398.14,41.27 398.14,43.81 D01.K2 | v310.51,98.43 307.98,100.97 307.98,102.87 317.5,112.4 321.31,112.4 321.94,113.03 323.21,113.03 323.85,113.67 v323.85,114.3 | v340.36,117.48 340.36,118.75 338.45,120.65 354.96,137.16 355.6,137.16 356.87,138.43 356.87,140.34 365.12,148.59 365.76,148.59 367.03,149.86 367.03,153.03 371.48,157.48 371.48,163.19 v394.97,186.69 | v377.19,208.91 377.19,213.36 v399.42,235.59
  Route15 0.152: v358.14,50.16 346.07,62.23 346.07,62.87 344.81,64.14 343.54,64.14 311.15,96.52 311.15,97.79 v310.51,98.43
  Bottom 0.152: v358.14,50.16 v381,27.3 | v323.85,114.3 323.85,116.84 323.21,117.48 323.21,119.38 324.49,120.65 317.5,127.64 318.77,128.91 320.68,127 320.68,126.37 321.31,125.73 324.49,125.73 328.93,130.18 335.28,123.83 335.28,123.19 340.36,118.11 v340.36,117.48 | v394.97,186.69 394.97,187.96 377.19,205.74 v377.19,208.91 | v399.42,235.59 405.13,241.3 399.42,247.02 399.42,249.56 398.78,250.19 A01.K2
-BAC4  (via drill 0.61)
  Top 0.152: v323.21,124.46 321.94,124.46 319.4,121.92 v318.77,121.92
  Route2 0.152: v244.47,196.85 244.47,202.56 247.65,205.74 247.65,208.91 256.54,217.81 256.54,218.44 257.81,219.71 261.62,219.71 262.25,220.34 268.61,220.34 269.88,221.62 269.88,226.69 279.4,236.22 285.75,236.22 302.26,252.73 308.61,252.73 314.96,259.08 321.31,259.08 327.66,265.43 334.01,265.43 340.36,271.78 348.62,271.78 354.33,266.06 356.24,267.97 358.77,267.97 367.03,259.71 368.94,261.62 371.48,261.62 392.43,240.66 394.33,242.57 396.88,242.57 398.14,243.84 A01.M2
  Route15 0.152: v344.17,102.87 349.25,102.87 352.43,99.7 352.43,99.06 354.33,97.16 354.96,97.16 379.1,73.03 381,73.03 384.18,69.85 384.18,68.58 398.14,54.61 396.24,52.7 396.24,48.89 396.88,48.26 396.88,43.81 398.14,42.55 398.14,38.73 D01.M2 | v307.34,132.08 307.34,132.72 296.55,143.51 294,143.51 287.02,150.5 286.38,150.5 269.88,167 269.88,172.09 269.24,172.72 263.52,172.72 262.89,173.36 262.25,173.36 260.99,174.62 260.99,175.9 257.81,179.07 257.81,179.71 253.37,184.15 252.73,184.15 244.47,192.41 v244.47,196.85
  Bottom 0.152: v344.17,102.87 343.54,102.87 323.21,123.19 v323.21,124.46 | v318.77,121.92 317.5,121.92 v307.34,132.08
-BAC5  (via drill 0.61)
  Top 0.152: v375.92,205.11 372.11,205.11 370.84,206.38 373.38,208.91 374.01,208.91 375.29,210.19 375.29,212.09 396.88,233.68 396.88,236.22 398.14,237.49 A01.P2
  Route2 0.152: v402.59,51.43 396.88,45.72 396.88,40.64 394.97,38.73 398.14,35.56 398.14,32.38 D01.P2 | v360.05,112.4 361.31,112.4 365.76,116.84 365.76,118.75 363.86,120.65 368.3,125.09 368.94,125.09 374.65,130.81 374.65,131.44 391.16,147.96 391.16,149.86 392.43,151.13 392.43,152.4 397.51,157.48 397.51,158.75 400.05,161.29 400.05,163.83 398.14,165.74 400.05,167.64 400.05,170.81 399.42,171.45 400.05,172.09 400.05,173.36 403.86,177.16 v403.86,177.8
  Route15 0.152: v371.48,95.89 371.48,100.33 367.03,104.78 366.39,104.78 360.05,111.12 v360.05,112.4 | v382.9,198.75 382.9,199.39 377.19,205.11 v375.92,205.11
  Bottom 0.152: v402.59,51.43 404.5,53.34 403.23,54.61 403.23,55.24 370.84,87.63 370.84,90.81 372.11,92.08 370.84,93.34 370.84,95.25 v371.48,95.89 | v403.86,177.8 403.86,178.44 396.88,185.42 394.97,185.42 393.7,186.69 394.33,187.33 393.7,187.96 393.7,188.59 383.54,198.75 v382.9,198.75
-BAC6  (via drill 0.61)
  Top 0.152: v364.49,63.5 364.49,64.14 373.38,73.03 v374.01,73.03 | v333.38,110.49 334.01,109.86 342.9,118.75 344.17,118.75 346.07,120.65 346.07,121.29 347.98,123.19 347.98,124.46 357.5,133.98 v357.5,134.62
  Route2 0.152: v357.5,134.62 361.95,139.06 361.95,147.96 371.48,157.48 371.48,163.19 393.7,185.42 394.97,185.42 396.88,187.33 396.88,187.96 397.51,188.59 397.51,190.5 400.05,193.04 400.05,196.22 398.78,197.49 403.86,202.56 403.86,204.47 400.69,207.65 404.5,211.46 404.5,222.89 397.51,229.87 398.78,231.14 A01.S2
  Route15 0.152: v353.69,87 353.06,87 333.38,106.68 v333.38,110.49
  Bottom 0.152: v364.49,63.5 364.49,62.87 372.11,55.24 372.11,54.61 398.14,28.58 398.14,26.04 D01.S2 | v374.01,73.03 373.38,73.03 370.2,76.2 370.2,77.47 365.12,82.55 358.14,82.55 v353.69,87
-BAC7  (via drill 0.61)
  Top 0.152: v367.03,13.97 377.19,13.97 381,17.78 387.35,17.78 391.16,21.59 394.97,21.59 D01.T2 | v346.07,196.85 347.98,196.85 349.88,198.75 351.79,198.75 353.69,196.85 361.31,204.47 361.95,204.47 365.76,208.28 367.67,208.28 377.19,217.81 377.19,219.71 382.27,224.79 382.27,226.06 387.35,231.14 v387.35,231.78
  Route2 0.152: v282.57,95.89 282.57,96.52 289.56,103.51 294.64,103.51 295.27,104.14 295.27,109.86 320.04,134.62 320.68,134.62 335.92,149.86 339.09,149.86 358.77,169.55 364.49,169.55 367.03,172.09 v367.03,172.72
  Route15 0.152: v367.03,13.97 362.58,13.97 320.68,55.88 320.68,61.59 320.04,62.23 320.04,62.87 308.61,74.3 306.07,74.3 300.99,79.38 300.99,80.01 298.45,82.55 294,82.55 282.57,93.98 v282.57,95.89
  Bottom 0.152: v367.03,172.72 365.76,172.72 346.07,192.41 v346.07,196.85 | v387.35,231.78 387.35,229.87 386.08,228.6 391.16,223.52 393.06,223.52 396.24,226.69 394.97,227.97 A01.T2
-BAC8  (via drill 0.61)
  Top 0.152: v356.24,90.17 357.5,90.17 361.95,94.62 v361.95,95.25 | v360.05,141.61 360.68,141.61 363.22,144.15 365.12,144.15 v405.13,184.15 | v394.97,205.11 394.97,211.46 389.89,216.53 394.97,221.62 A01.V2
  Route2 0.152: v342.9,117.48 342.9,120.02 344.17,121.29 344.81,121.29 346.07,122.56 346.07,128.27 354.96,137.16 355.6,137.16 v360.05,141.61
  Route15 0.152: v354.96,82.55 356.24,83.82 355.6,84.46 355.6,88.27 356.87,89.54 v356.24,90.17
  Bottom 0.152: v354.96,82.55 358.14,79.38 358.14,76.2 364.49,69.85 364.49,69.22 365.76,67.95 366.39,67.95 369.57,64.77 374.65,64.77 396.88,42.55 396.88,30.48 405.13,22.23 399.42,16.51 395.61,16.51 D01.V2 | v361.95,95.25 361.95,96.52 349.88,108.59 349.25,108.59 347.98,109.86 347.98,111.12 342.9,116.21 v342.9,117.48 | v405.13,184.15 396.88,192.41 396.88,196.22 400.69,200.03 395.61,205.11 v394.97,205.11
-BAC9  (via drill 0.61)
  Top 0.152: v371.48,73.03 372.11,73.03 384.18,85.09 v384.18,88.9 | v389.25,102.87 v381.63,95.25 | v368.94,127 370.2,127 381,137.8 381,139.06 v389.89,147.96 | v385.44,184.15 394.33,193.04 394.33,193.68 395.61,194.94 396.88,194.94 v398.14,196.22
  Route2 0.152: v389.89,147.96 389.25,148.59 391.8,151.13 391.8,152.4 396.24,156.84 396.24,157.48 396.88,158.12 v396.88,167.64
  Route15 0.152: v398.14,196.22 398.14,197.49 401.32,200.66 374.01,227.97 374.01,229.24 379.73,234.95 371.48,243.21 371.48,252.73 383.54,264.8 382.27,266.06 A02.D2
  Bottom 0.152: v371.48,73.03 373.38,71.12 374.65,71.12 382.27,63.5 382.27,60.96 D02.D2 | v384.18,88.9 384.18,92.71 v381.63,95.25 | v389.25,102.87 389.89,102.87 391.8,104.78 384.18,112.4 378.46,112.4 371.48,119.38 371.48,124.46 v368.94,127 | v396.88,167.64 396.88,172.72 v385.44,184.15
-BAC10  (via drill 0.61)
  Top 0.152: v393.06,150.5 393.06,153.67 396.88,157.48 396.88,163.19 v405.13,171.45 | v368.94,212.72 368.94,218.44 396.88,246.38 396.88,255.27 387.35,264.8 386.08,263.52 A02.E2
  Route2 0.152: v391.16,66.04 386.08,60.96 386.08,57.78 D02.E2 | v358.77,95.25 358.77,96.52 369.57,107.32 369.57,108.59 374.65,113.67 374.65,116.84 373.38,118.11 397.51,142.24 v397.51,142.88
  Route15 0.152: v391.16,66.04 391.16,67.31 375.29,83.19 370.2,83.19 366.39,87 365.76,87 358.77,93.98 v358.77,95.25 | v383.54,193.04 371.48,205.11 371.48,210.19 v368.94,212.72
  Bottom 0.152: v397.51,142.88 397.51,146.05 v393.06,150.5 | v405.13,171.45 v383.54,193.04
-BAC11  (via drill 0.61)
  Top 0.152: v391.8,76.2 391.16,75.57 396.88,69.85 396.88,66.04 394.97,64.14 394.97,62.87 386.08,53.98 386.08,51.43 D02.H2 | v316.87,218.44 314.32,220.98 318.13,224.79 318.13,226.69 313.06,231.78 346.07,264.8 352.43,264.8 358.77,271.14 365.12,271.14 365.76,271.78 374.01,271.78 382.9,262.89 381,260.99 381,259.71 384.18,256.54 385.44,257.81 A02.H2
  Route2 0.152: v320.68,197.49 320.68,201.3 v325.75,206.38
  Route15 0.152: v391.8,76.2 391.8,84.46 396.24,88.9 v396.88,88.9 | v393.06,97.16 381,109.22 381,109.86 371.48,119.38 371.48,122.56 382.27,133.35 375.29,140.34 375.29,141.61 v370.2,146.69
  Bottom 0.152: v396.88,88.9 396.88,92.71 393.7,95.89 393.7,96.52 v393.06,97.16 | v370.2,146.69 370.2,148.59 321.31,197.49 v320.68,197.49 | v325.75,206.38 325.75,208.28 321.94,212.09 321.94,213.36 v316.87,218.44
-BMB0  (via drill 0.61)
  Route2 0.152: v325.12,100.33 325.12,101.6 327.66,104.14 327.66,106.05 325.75,107.95 337.19,119.38 v337.82,119.38 | v273.05,180.97 273.05,182.88 271.14,184.78 273.05,186.69 273.05,187.33 274.32,188.59 275.59,188.59 282.57,195.58 282.57,196.85 v283.85,198.12 | v261.62,230.5 261.62,231.78 271.14,241.3 277.5,234.95 314.32,271.78 321.31,271.78 327.66,278.13 339.73,278.13 340.36,278.76 354.96,278.76 368.3,265.43 369.57,266.7 A03.D2
  Route15 0.152: v325.12,100.33 326.39,100.33 339.73,87 339.73,86.36 343.54,82.55 349.25,82.55 354.96,76.84 354.96,74.93 358.14,71.75 358.14,68.58 363.22,63.5 365.12,65.41 368.94,65.41 370.2,64.14 370.2,60.96 D03.D2 | v337.82,119.38 337.82,121.29 320.68,138.43 320.68,139.7 315.6,144.78 315.6,146.05 295.27,166.37 288.93,166.37 275.59,179.71 274.32,179.71 v273.05,180.97
  Bottom 0.152: v283.85,198.12 282.57,199.39 282.57,206.38 276.23,212.72 276.23,217.17 262.89,230.5 v261.62,230.5
-BMB1  (via drill 0.61)
  Top 0.152: v282.57,146.69 282.57,150.5 292.1,160.02 297.81,160.02 v305.44,167.64 | v320.68,187.33 320.68,187.96 321.31,188.59 v325.75,188.59 | v371.48,259.71 371.48,260.99 373.38,262.89 A03.E2
  Route2 0.152: v305.44,167.64 305.44,168.28 307.98,170.81 307.98,176.53 316.87,185.42 318.77,185.42 v320.68,187.33 | v325.75,188.59 326.39,188.59 333.38,195.58 333.38,201.3 v339.09,207.01 | v325.75,220.34 324.49,220.34 322.58,222.25 340.36,240.03 346.71,240.03 353.06,246.38 358.77,246.38 371.48,259.08 v371.48,259.71
  Route15 0.152: v282.57,146.69 288.29,140.97 288.29,139.06 320.68,106.68 320.68,100.33 341.63,79.38 341.63,78.11 342.26,77.47 342.26,76.84 347.98,71.12 349.25,71.12 358.14,62.23 364.49,62.23 368.94,57.78 372.75,57.78 D03.E2
  Bottom 0.152: v339.09,207.01 v325.75,220.34
-BMB2  (via drill 0.61)
  Top 0.152: v392.43,141.61 392.43,144.78 393.7,146.05 393.7,147.32 v404.5,158.12
  Route2 0.152: v403.23,128.91 401.32,127 403.86,124.46 403.86,123.19 398.78,118.11 400.05,116.84 400.05,113.67 398.14,111.76 400.05,109.86 400.05,107.32 397.51,104.78 397.51,103.51 382.9,88.9 384.18,87.63 384.18,85.09 381.63,82.55 386.08,78.11 386.08,75.57 384.81,74.3 384.81,71.75 384.18,71.12 384.18,65.41 373.38,54.61 373.38,51.43 D03.H2 | v393.7,169.55 393.7,173.36 403.86,183.52 v403.86,184.15 | v358.77,233.05 358.14,233.68 358.77,234.31 358.77,240.03 371.48,252.73 371.48,255.27 372.75,256.54 A03.H2
  Bottom 0.152: v403.23,128.91 404.5,130.18 401.95,132.72 401.32,132.72 393.7,140.34 393.7,140.97 393.06,141.61 v392.43,141.61 | v404.5,158.12 404.5,158.75 v393.7,169.55 | v403.86,184.15 403.86,184.78 396.24,192.41 395.61,192.41 393.7,194.31 393.7,194.94 361.95,226.69 361.95,227.97 358.77,231.14 v358.77,233.05
-BMB3  (via drill 0.61)
  Top 0.152: v401.32,58.42 397.51,58.42 394.33,55.24 393.7,55.24 377.19,38.73 373.38,38.73 D03.M2 | v395.61,109.22 400.05,113.67 400.05,114.94 v398.78,116.21 | v396.88,184.15 396.88,187.96 397.51,188.59 397.51,190.5 400.05,193.04 400.05,196.22 398.78,197.49 403.86,202.56 403.86,204.47 400.05,208.28 v403.23,211.46
  Route2 0.152: v374.01,91.44 374.01,92.71 384.18,102.87 387.99,102.87 389.25,101.6 393.7,106.05 393.7,107.32 v395.61,109.22 | v387.35,146.69 387.35,147.32 391.16,151.13 391.16,153.03 386.08,158.12 387.35,159.39 387.35,164.47 386.71,165.1 387.35,165.74 387.35,166.37 390.52,169.55 390.52,170.81 391.16,171.45 391.16,172.09 388.62,174.62 396.88,182.88 v396.88,184.15
  Route15 0.152: v403.23,211.46 403.23,217.81 394.97,226.06 394.97,226.69 393.7,227.97 392.43,227.97 377.19,243.21 374.01,243.21 373.38,243.84 A03.M2
  Bottom 0.152: v401.32,58.42 400.69,58.42 389.89,69.22 389.89,74.3 378.46,85.73 378.46,87 v374.01,91.44 | v398.78,116.21 398.78,118.75 400.69,120.65 399.42,121.92 397.51,121.92 396.24,120.65 393.7,123.19 393.7,125.73 394.97,127 387.35,134.62 387.35,135.89 386.71,136.53 386.71,138.43 387.99,139.7 387.35,140.34 v387.35,146.69
-BMB3\  (via drill 0.61)
  Top 0.152: v369.57,81.28 369.57,83.19 v376.56,90.17
  Route2 0.152: v376.56,90.17 377.82,90.17 384.18,96.52 389.89,96.52 396.88,103.51 396.88,112.4 392.43,116.84 397.51,121.92 397.51,123.19 v400.69,126.37 | v376.56,180.97 376.56,181.61 394.33,199.39 394.33,201.93 392.43,203.84 394.33,205.74 394.33,212.09 387.99,218.44 394.33,224.79 394.33,226.06 v393.7,226.69
  Route15 0.152: v369.57,81.28 370.2,80.65 370.2,73.03 371.48,71.75 371.48,68.58 382.9,57.15 372.75,46.99 372.75,45.09 D03.K2 | v400.69,126.37 401.32,127 398.78,129.54 398.78,130.81 396.88,132.72 396.88,142.24 396.24,142.88 396.24,151.13 398.14,153.03 381,170.18 381,173.99 382.27,175.26 v376.56,180.97
  Bottom 0.152: v393.7,226.69 393.7,227.33 374.01,247.02 374.01,249.56 373.38,250.19 A03.K2
-BMB4  (via drill 0.61)
  Top 0.152: v319.4,102.87 320.04,102.87 v355.6,138.43 | v307.98,189.23 307.98,195.58 327.02,214.63 327.02,215.27 334.64,222.89 v334.64,223.52 | v351.15,220.34 352.43,220.34 365.76,233.68 370.84,233.68 371.48,234.31 373.38,232.41 A03.S2
  Route2 0.152: v334.64,223.52 334.64,220.34 341,214 346.07,219.08 349.88,219.08 v351.15,220.34
  Route15 0.152: v363.86,36.83 363.86,38.73 372.75,47.62 358.77,61.59 353.06,61.59 346.07,68.58 346.07,72.39 341,77.47 341,79.38 320.04,100.33 320.04,102.23 v319.4,102.87
  Bottom 0.152: v363.86,36.83 364.49,36.83 372.75,28.58 372.75,26.04 D03.S2 | v355.6,138.43 356.87,139.7 354.96,141.61 352.43,141.61 339.09,154.94 339.09,155.58 337.82,156.84 337.19,156.84 307.98,186.06 v307.98,189.23
-BMB4\  (via drill 0.61)
  Top 0.152: v388.62,71.75 387.99,71.12 394.33,64.77 394.33,62.87 384.18,52.7 384.18,46.35 377.19,39.37 372.11,39.37 370.84,38.1 372.75,36.2 372.75,32.38 D03.P2 | v377.82,84.46 377.82,85.09 379.73,87 380.37,87 384.81,91.44 385.44,91.44 390.52,96.52 390.52,97.79 391.8,99.06 v391.8,99.7 | v385.44,109.86 385.44,110.49 393.7,118.75 399.42,118.75 v405.13,124.46 | v387.35,187.33 387.35,189.23 386.08,190.5 394.97,199.39 394.97,200.66 396.88,202.56 v396.88,209.55
  Route15 0.152: v391.8,99.7 391.16,99.7 384.18,106.68 384.18,108.59 v385.44,109.86 | v405.13,124.46 404.5,124.46 399.42,129.54 399.42,130.81 401.32,132.72 400.05,133.98 400.05,135.89 399.42,136.53 399.42,138.43 400.69,139.7 400.69,140.97 400.05,141.61 400.05,151.77 396.88,154.94 396.88,160.66 386.71,170.81 386.71,172.09 392.43,177.8 386.71,183.52 386.71,185.42 387.99,186.69 v387.35,187.33
  Bottom 0.152: v388.62,71.75 388.62,73.66 v377.82,84.46 | v396.88,209.55 393.7,212.72 393.7,214.63 381.63,226.69 381.63,227.33 379.1,229.87 378.46,229.87 374.01,234.31 374.01,236.86 373.38,237.49 A03.P2
-BMB5  (via drill 0.61)
  Route2 0.152: v382.9,120.02 382.9,121.29 396.88,135.25 396.88,140.97 398.78,142.88 398.78,153.03 403.23,157.48 403.23,158.12 v405.13,160.02
  Route15 0.152: v405.13,80.65 405.13,74.3 399.42,68.58 399.42,66.04 403.86,61.59 403.86,60.32 404.5,59.69 396.88,52.07 396.88,48.89 404.5,41.27 400.05,36.83 397.51,36.83 395.61,38.73 373.38,16.51 370.2,16.51 D03.V2 | v393.7,98.43 393.7,100.97 394.97,102.23 381,116.21 381,118.11 v382.9,120.02 | v400.05,174.62 400.05,177.16 396.88,180.34 396.88,182.25 401.95,187.33 396.88,192.41 396.88,199.39 391.8,204.47 390.52,204.47 375.92,219.08 372.11,219.08 369.57,221.62 A03.V2
  Bottom 0.152: v405.13,80.65 405.13,85.09 396.24,93.98 396.24,95.25 393.7,97.79 v393.7,98.43 | v405.13,160.02 403.86,160.02 399.42,164.47 399.42,167 401.32,168.91 399.42,170.81 399.42,171.45 400.05,172.09 v400.05,174.62
-BMB5\  (via drill 0.61)
  Top 0.152: v295.27,114.3 295.27,116.21 v305.44,126.37 | v298.45,147.32 304.8,153.67 304.8,154.94 307.98,158.12 307.98,163.83 320.68,176.53 320.68,181.61 v321.94,182.88 | v318.13,200.66 316.23,202.56 327.66,214 328.3,214 331.47,217.17 331.47,218.44 340.36,227.33 345.44,227.33 349.25,231.14 v349.25,231.78
  Route2 0.152: v349.25,231.78 351.15,231.78 360.68,222.25 365.76,227.33 368.94,227.33 369.57,227.97 A03.T2
  Route15 0.152: v321.94,67.95 320.68,69.22 320.68,77.47 v318.77,79.38 | v321.94,182.88 321.94,184.78 313.69,193.04 313.69,194.94 318.77,200.03 v318.13,200.66
  Bottom 0.152: v321.94,67.95 321.94,67.31 327.02,62.23 327.02,61.59 333.38,55.24 333.38,49.53 356.24,26.67 361.95,26.67 365.76,22.86 369.57,22.86 D03.T2 | v318.77,79.38 318.13,79.38 314.32,83.19 312.42,83.19 307.98,87.63 307.98,93.98 297.81,104.14 297.81,106.05 299.72,107.95 296.55,111.12 296.55,112.4 295.27,113.67 v295.27,114.3 | v305.44,126.37 305.44,128.91 304.8,129.54 304.8,132.08 308.61,135.89 308.61,137.16 v298.45,147.32
-BMB6  (via drill 0.61)
  Top 0.152: v323.85,88.9 323.85,88.27 320.04,84.46 314.96,84.46 313.69,83.19 310.51,83.19 309.88,82.55 v307.98,82.55 | v249.56,144.15 250.19,144.15 280.04,173.99 280.04,175.26 278.13,177.16 281.94,180.97 v282.57,180.97
  Route2 0.152: v273.05,195.58 271.78,196.85 276.86,201.93 281.94,201.93 285.75,205.74 285.75,210.19 289.56,214 289.56,215.27 302.26,227.97 303.53,227.97 306.7,231.14 306.7,233.05 313.06,239.4 314.32,239.4 314.96,240.03 321.31,240.03 327.66,246.38 335.92,246.38 337.82,244.47 352.43,259.08 353.69,259.08 356.24,261.62 358.77,261.62 360.05,262.89 A04.E2
  Route15 0.152: v323.85,88.9 324.49,88.27 323.21,87 323.21,85.09 326.39,81.92 328.93,81.92 339.09,71.75 342.26,71.75 356.87,57.15 360.05,57.15 D04.E2 | v307.98,82.55 299.08,82.55 298.45,83.19 294,83.19 292.1,85.09 292.1,87.63 293.37,88.9 291.46,90.81 290.83,90.81 288.93,92.71 288.93,93.34 286.38,95.89 285.75,95.89 284.48,97.16 284.48,99.06 279.4,104.14 279.4,104.78 278.13,106.05 276.86,106.05 266.7,116.21 266.7,120.02 267.97,121.29 250.19,139.06 250.19,143.51 v249.56,144.15
  Bottom 0.152: v282.57,180.97 282.57,186.06 v273.05,195.58
-BMB6\  (via drill 0.61)
  Top 0.152: v361.31,66.67 357.5,62.87 357.5,60.96 D04.D2 | v342.9,228.6 342.9,229.87 355.6,242.57 355.6,243.84 358.77,247.02 358.77,260.35 v360.05,261.62
  Route2 0.152: v333.38,104.78 333.38,109.22 340.36,116.21 342.26,116.21 344.17,114.3 349.25,119.38 349.25,122.56 347.98,123.83 362.58,138.43 363.22,138.43 364.49,139.7 364.49,142.24 368.3,146.05 368.3,147.32 378.46,157.48 379.73,157.48 v381,158.75 | v356.24,205.74 356.24,219.71 350.52,225.43 v349.25,224.16
  Route15 0.152: v361.31,66.67 358.77,69.22 358.77,74.3 336.55,96.52 336.55,97.79 333.38,100.97 v333.38,104.78 | v381,158.75 381,160.66 382.27,161.93 374.01,170.18 373.38,170.18 372.11,171.45 372.11,173.36 371.48,173.99 371.48,179.71 368.3,182.88 368.3,184.78 370.2,186.69 368.94,187.96 368.94,188.59 358.77,198.75 358.77,203.84 356.87,205.74 v356.24,205.74
  Bottom 0.152: v349.25,224.16 346.71,224.16 342.9,227.97 v342.9,228.6 | v360.05,261.62 358.77,262.89 358.77,264.8 357.5,266.06 A04.D2
-BMB7  (via drill 0.61)
  Top 0.152: v371.48,59.69 368.3,56.52 368.3,55.24 360.68,47.62 360.68,45.09 D04.K2
  Route2 0.152: v371.48,59.69 376.56,64.77 377.19,64.77 381.63,69.22 381.63,71.12 382.27,71.75 382.27,73.03 v384.81,75.57 | v372.11,93.34 369.57,95.89 375.92,102.23 v375.92,102.87 | v298.45,198.75 305.44,205.74 305.44,219.08 307.98,221.62 307.98,226.69 320.68,239.4 327.02,239.4 327.66,240.03 334.01,240.03 340.36,246.38 346.71,246.38 353.06,252.73 358.77,252.73 360.05,251.46 A04.K2
  Route15 0.152: v375.92,102.87 375.29,102.87 371.48,106.68 371.48,111.12 372.75,112.4 368.3,116.84 368.3,117.48 367.03,118.75 365.76,118.75 346.07,138.43 346.07,143.51 v344.81,144.78 | v336.55,155.58 336.55,157.48 323.21,170.81 323.21,173.36 324.49,174.62 323.21,175.9 318.13,175.9 297.81,196.22 297.81,198.12 v298.45,198.75
  Bottom 0.152: v384.81,75.57 383.54,75.57 371.48,87.63 371.48,90.17 373.38,92.08 v372.11,93.34 | v344.81,144.78 344.81,148.59 339.09,154.31 337.82,154.31 v336.55,155.58
-BMB7\  (via drill 0.61)
  Top 0.152: v274.32,187.33 274.95,187.33 276.86,189.23 v277.5,189.23 | v259.71,196.22 259.71,197.49 v283.21,220.98
  Route2 0.152: v287.65,87.63 287.65,88.9 289.56,90.81 290.83,90.81 292.1,92.08 292.1,94.62 295.27,97.79 295.27,103.51 298.45,106.68 298.45,109.86 297.18,111.12 314.96,128.91 320.68,128.91 327.66,135.89 329.56,135.89 v330.2,136.53 | v283.21,220.98 292.1,229.87 297.81,229.87 327.02,259.08 334.01,259.08 340.36,265.43 349.25,265.43 351.15,263.52 353.06,265.43 360.68,265.43 363.22,262.89 361.31,260.99 361.31,258.44 360.68,257.81 A04.H2
  Route15 0.152: v323.85,71.75 329.56,71.75 330.83,70.48 332.11,70.48 333.38,69.22 333.38,68.58 356.87,45.09 360.05,48.26 360.05,50.16 D04.H2
  Bottom 0.152: v323.85,71.75 308.61,71.75 304.8,75.57 304.8,76.84 297.81,83.82 292.1,83.82 288.29,87.63 v287.65,87.63 | v330.2,136.53 328.93,136.53 323.85,141.61 321.94,141.61 315.6,147.96 313.69,147.96 v274.32,187.33 | v277.5,189.23 277.5,190.5 275.59,192.41 266.7,192.41 264.8,190.5 259.71,195.58 v259.71,196.22
-BMB8  (via drill 0.61)
  Top 0.152: v368.3,130.18 367.03,130.18 364.49,127.64 364.49,125.73 369.57,120.65 381.63,132.72 381.63,135.25 380.37,136.53 391.16,147.32 391.16,150.5 391.8,151.13 391.8,153.03 389.25,155.58 394.33,160.66 v394.97,160.66 | v356.24,232.41 356.87,232.41 358.77,234.31 358.77,236.22 360.05,237.49 A04.P2
  Route2 0.152: v337.82,90.17 337.19,90.17 335.28,92.08 355.6,112.4 355.6,113.67 358.77,116.84 358.77,121.92 365.76,128.91 367.03,128.91 v368.3,130.18 | v394.97,160.66 394.33,161.29 394.33,163.83 392.43,165.74 396.88,170.18 v396.88,174.62
  Route15 0.152: v374.01,46.35 375.92,44.45 363.86,32.38 360.68,32.38 D04.P2 | v396.88,174.62 396.88,179.71 386.71,189.87 386.71,191.77 391.8,196.85 v356.24,232.41
  Bottom 0.152: v374.01,46.35 374.01,47.62 371.48,50.16 371.48,55.24 360.05,66.67 360.05,67.95 358.77,69.22 358.77,71.12 354.96,74.93 354.96,76.84 349.25,82.55 345.44,82.55 342.9,85.09 342.9,85.73 341.63,87 340.36,87 337.82,89.54 v337.82,90.17
-BMB8\  (via drill 0.61)
  Top 0.152: v334.01,213.36 334.01,215.27 356.24,237.49 356.24,240.03 354.96,241.3 356.24,242.57 358.77,242.57 360.05,243.84 A04.M2
  Route2 0.152: v280.04,127.64 281.94,127.64 295.27,140.97 300.36,140.97 306.7,147.32 306.7,148.59 311.15,153.03 311.15,153.67 317.5,160.02 317.5,161.29 320.68,164.47 320.68,170.18 330.83,180.34 330.83,181.61 321.94,190.5 333.38,201.93 333.38,212.72 v334.01,213.36
  Route15 0.152: v327.02,75.57 325.12,75.57 314.32,86.36 314.32,87 285.75,115.57 285.75,116.84 282.57,120.02 282.57,125.09 v280.04,127.64
  Bottom 0.152: v327.02,75.57 333.38,69.22 333.38,68.58 346.07,55.88 346.07,49.53 356.87,38.73 360.05,38.73 D04.M2
-BMB9  (via drill 0.61)
  Top 0.152: v323.85,56.52 324.49,56.52 336.55,68.58 336.55,69.85 v339.73,73.03 | v216.53,213.36 217.81,213.36 263.52,259.08 264.8,259.08 267.33,261.62 273.05,261.62 282.57,271.14 288.93,271.14 289.56,271.78 294.64,271.78 v300.99,278.13
  Route15 0.152: v323.85,56.52 324.49,55.88 326.39,55.88 356.24,26.04 360.05,26.04 D04.S2 | v339.73,73.03 342.26,75.57 340.36,77.47 340.36,79.38 332.74,87 327.66,87 297.81,116.84 297.81,119.38 299.08,120.65 294.64,125.09 294,125.09 292.74,126.37 292.74,127.64 287.02,133.35 286.38,133.35 285.12,134.62 285.12,136.53 282.57,139.06 282.57,141.61 271.78,152.4 271.78,153.03 269.88,154.94 269.88,160.02 v216.53,213.36 | v300.99,278.13 304.8,278.13 314.96,267.97 320.68,267.97 352.43,236.22 353.69,236.22 358.14,231.78 360.05,231.78 A04.S2
-BMB10  (via drill 0.61)
  Top 0.152: v400.05,50.16 398.78,48.89 393.7,48.89 360.68,15.88 357.5,19.05 357.5,21.59 D04.T2 | v381,71.75 382.27,71.75 383.54,73.03 384.81,73.03 401.32,89.54 v401.32,90.17 | v374.65,168.28 375.92,168.28 392.43,184.78 v392.43,185.42 | v389.89,257.81 389.25,257.81 361.95,230.5 360.05,230.5 357.5,227.97 A04.T2
  Route2 0.152: v396.88,99.06 396.88,102.23 398.14,103.51 398.14,104.78 403.86,110.49 403.86,112.4 v401.32,114.94 | v392.43,185.42 391.16,185.42 386.08,190.5 394.97,199.39 394.97,200.66 400.05,205.74 400.05,209.55 403.23,212.72 403.23,217.81 394.97,226.06 396.88,227.97 396.88,239.4 400.69,243.21 400.69,245.75 389.25,257.18 v389.89,257.81
  Route15 0.152: v401.32,114.94 393.7,122.56 393.7,125.09 398.14,129.54 393.7,133.98 393.7,139.06 395.61,140.97 388.62,147.96 388.62,149.22 377.19,160.66 376.56,160.66 375.29,161.93 375.29,163.19 374.01,164.47 374.01,166.37 375.29,167.64 v374.65,168.28
  Bottom 0.152: v400.05,50.16 400.05,52.07 383.54,68.58 382.9,68.58 381.63,69.85 381.63,71.12 v381,71.75 | v401.32,90.17 400.69,90.17 396.88,93.98 v396.88,99.06
-BMB11  (via drill 0.61)
  Top 0.152: v219.71,150.5 222.25,153.03 222.25,153.67 292.1,223.52 293.37,223.52 v295.27,225.43
  Route2 0.152: v317.5,209.55 318.13,209.55 329.56,220.98 329.56,222.89 333.38,226.69 339.73,226.69 340.36,227.33 349.25,227.33 355.6,220.98 356.87,222.25 A04.V2
  Route15 0.152: v240.03,117.48 244.47,113.03 244.47,106.68 251.46,99.7 251.46,98.43 252.73,97.16 253.37,97.16 346.07,4.45 356.87,15.24 D04.V2 | v295.27,225.43 295.27,224.16 299.08,220.34 300.36,220.34 311.15,209.55 v317.5,209.55
  Bottom 0.152: v240.03,117.48 231.78,125.73 231.78,137.8 219.71,149.86 v219.71,150.5
-BRK_IN_PRG  (via drill 0.61)
  Top 0.152: v393.7,221.62 381.63,209.55 381.63,205.74 375.92,200.03 381,194.94 381,194.31 384.18,191.14 384.18,189.87 383.54,189.23 378.46,189.23 370.2,180.97 370.2,178.44 B03.L2 | v268.61,289.56 266.06,289.56 264.8,290.83 263.52,289.56 256.54,289.56 255.91,290.19 252.73,290.19 250.82,288.29 244.47,288.29 v238.76,282.57
  Route2 0.152: v205.74,290.19 198.12,282.57 197.49,282.57 195.58,280.67 190.5,280.67 170.81,260.99 170.81,258.44 170.18,257.81 A19.H2
  Bottom 0.152: v393.7,221.62 393.7,222.89 398.78,227.97 358.77,267.97 353.06,267.97 337.19,283.84 318.13,283.84 317.5,284.48 311.79,284.48 310.51,285.75 295.91,285.75 295.27,286.38 290.19,286.38 289.56,287.02 282.57,287.02 280.67,288.92 269.24,288.92 v268.61,289.56 | v238.76,282.57 232.41,282.57 231.14,283.84 227.33,283.84 224.16,287.02 215.26,287.02 214,288.29 212.09,288.29 211.46,288.92 207.01,288.92 v205.74,290.19
-IM0  (via drill 0.61)
  Top 0.152: v347.35,160.02 345.44,161.93 349.25,165.74 349.25,166.37 355.6,172.72 357.5,172.72 358.77,173.99 358.77,175.9 362.58,179.71 v363.22,179.71 | v356.24,200.66 349.88,207.01 354.96,212.09 354.96,216.53 v371.48,233.05
  Route2 0.152: v328.3,80.65 328.3,83.82 330.2,85.73 330.2,87 331.47,88.27 331.47,89.54 333.38,91.44 333.38,102.87 342.9,112.4 343.54,112.4 349.25,118.11 349.25,118.75 349.88,119.38 350.52,119.38 351.79,120.65 351.79,121.92 368.94,139.06 368.94,140.34 367.03,142.24 v366.39,141.61
  Route15 0.152: v366.39,141.61 357.5,150.5 356.24,150.5 347.35,159.39 v347.35,160.02 | v363.22,179.71 363.22,181.61 361.31,183.52 361.31,186.06 363.22,187.96 358.77,192.41 358.77,197.49 356.24,200.03 v356.24,200.66 | v371.48,233.05 368.94,233.05 358.77,243.21 358.77,249.56 346.07,262.25 346.07,264.8 344.81,266.06 A05.D2
  Bottom 0.152: v328.3,80.65 328.3,80.01 340.36,67.95 341,67.95 346.07,62.87 346.07,62.23 344.81,60.96 D05.D2
-IM1  (via drill 0.61)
